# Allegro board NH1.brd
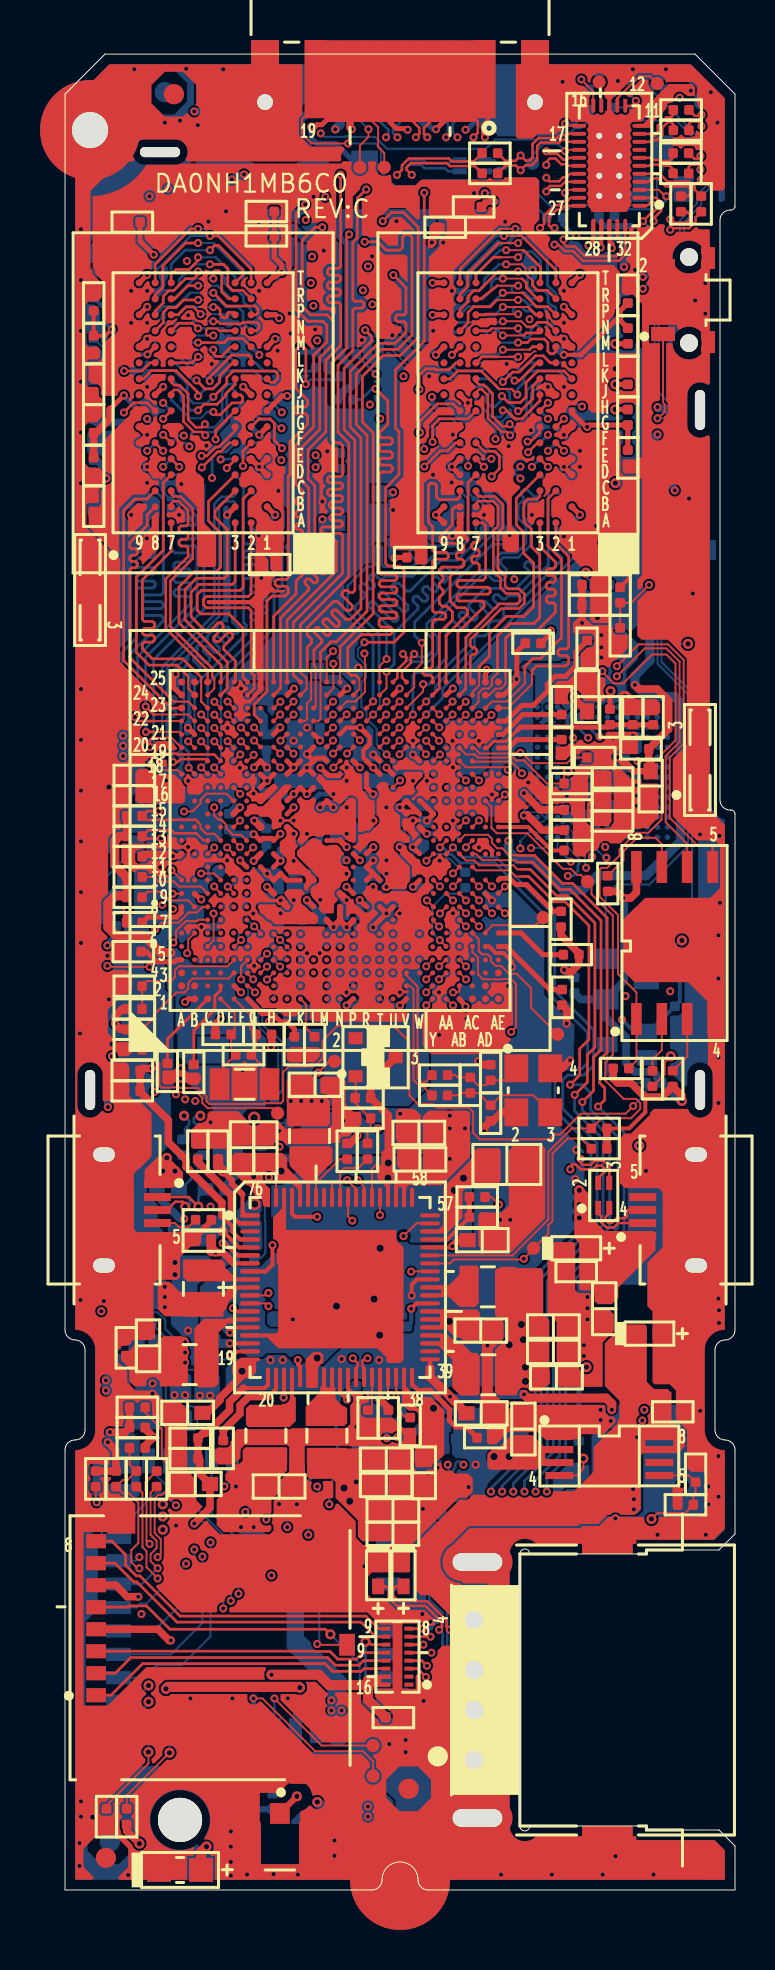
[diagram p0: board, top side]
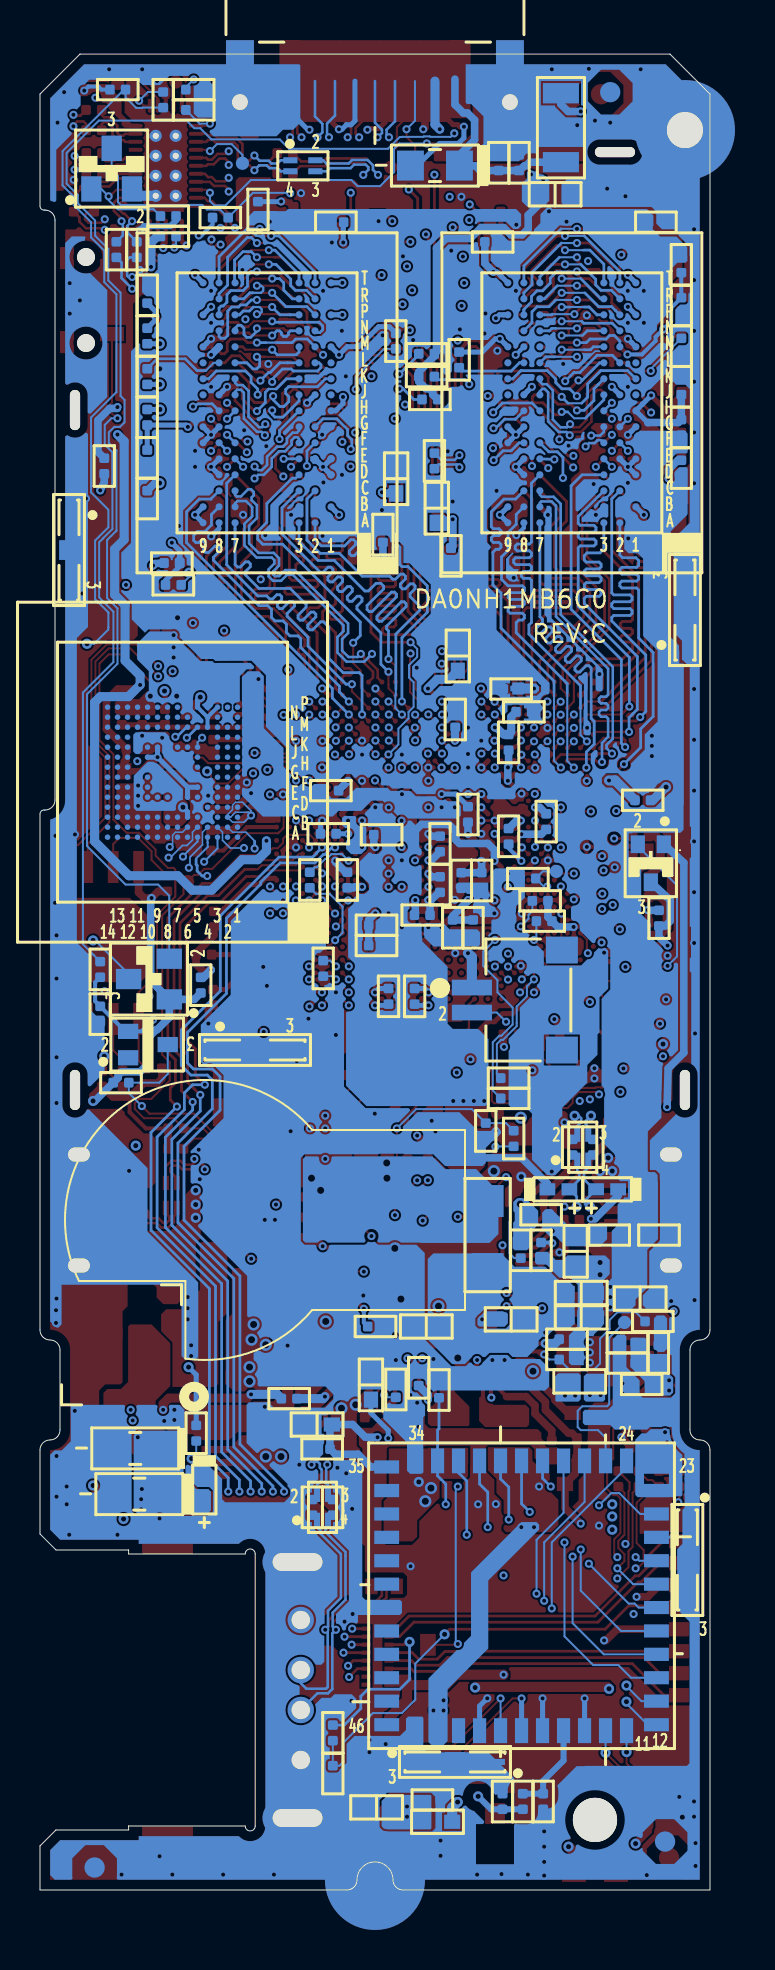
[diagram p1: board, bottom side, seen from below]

Outline 33.5 x 91.8 mm; copper layers: TOP, GND, IN1, IN2, VCC, BOTTOM. Coordinates in mm from the lower left corner of the outline.
Outline path: 0,89.8 2,91.8 31.5,91.8 33.5,89.8 33.5,84.2 arc(33.44,84.06) 33.3,84 33.25,84 arc(32.9,83.85) 32.75,83.5 32.75,54.5 arc(32.9,54.15) 33.25,54 33.3,54 arc(33.44,53.94) 33.5,53.8 33.5,28 arc(33.35,27.65) 33,27.5 arc(32.65,27.35) 32.5,27 32.5,23 arc(32.65,22.65) 33,22.5 arc(33.35,22.35) 33.5,22 33.5,17.8 32.7,17 29.07,17 29.07,16.8 23.24,16.8 arc(22.99,17.05) 22.74,16.8 22.74,3.2 arc(22.99,2.95) 23.24,3.2 29.07,3.2 29.07,3 32.7,3 33.5,2.2 33.5,0 18.15,0 arc(17.8,0.15) 17.65,0.5 arc(16.75,1.4) 15.85,0.5 arc(15.7,0.15) 15.35,0 0,0 0,22 arc(0.15,22.35) 0.5,22.5 arc(0.85,22.65) 1,23 1,27 arc(0.85,27.35) 0.5,27.5 arc(0.15,27.65) 0,28 0,89.8

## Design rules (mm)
constraint set DEFAULT: min track width 0.102
net group DFP-S4(3: nets DDI0_HDMI_SCL DDI0_HDMI_SDA
net group DFP-S4(6)W5.15(4.6)-T12B: nets M0_CLK0_DN M0_CLK0_DP M0_DQS0_DN M0_DQS0_DP M0_DQS1_DN M0_DQS1_DP M0_DQS2_DN M0_DQS2_DP M0_DQS3_DN M0_DQS3_DP M0_DQS4_DN M0_DQS4_DP M0_DQS5_DN M0_DQS5_DP M0_DQS6_DN M0_DQS6_DP M0_DQS7_DN M0_DQS7_DP PMIC_USB2_DN PMIC_USB2_DP
net group DFP-S4W5.14(4.6)-T12B: nets DDI0_HDMI_CLK_DN DDI0_HDMI_CLK_DN_ALS DDI0_HDMI_CLK_DN_CH DDI0_HDMI_CLK_DP DDI0_HDMI_CLK_DP_ALS DDI0_HDMI_CLK_DP_CH DDI0_HDMI_D0_DN DDI0_HDMI_D0_DN_ALS DDI0_HDMI_D0_DP DDI0_HDMI_D0_DP_ALS DDI0_HDMI_D1_DN DDI0_HDMI_D1_DN_ALS DDI0_HDMI_D1_DP DDI0_HDMI_D1_DP_ALS DDI0_HDMI_D2_DN DDI0_HDMI_D2_DN_ALS DDI0_HDMI_D2_DP DDI0_HDMI_D2_DP_ALS
net group DFP-S6W5.14(4.6)-T12B: nets DDI0_TX0_DN DDI0_TX0_DP DDI0_TX1_DN DDI0_TX1_DP DDI0_TX2_DN DDI0_TX2_DP DDI0_TX3_DN DDI0_TX3_DP
net group GND: nets +V1P0A +V1P0SX +V1P2SX +V1P8A +V3P3A +V_VCC +V_VNN +VDDI_EMMC +VDDQ GND
net group W5.5(4)-T12B: nets EMMC_CLK EMMC_CMD EMMC_DATA_0 EMMC_DATA_1 EMMC_DATA_2 EMMC_DATA_3 EMMC_DATA_4 EMMC_DATA_5 EMMC_DATA_6 EMMC_DATA_7 M0_BS0 M0_BS1 M0_BS2 M0_CASB M0_CKE0 M0_CS0_B M0_DATA0 M0_DATA1 M0_DATA2 M0_DATA3 M0_DATA4 M0_DATA5 M0_DATA6 M0_DATA7 M0_DATA8 M0_DATA9 M0_DATA10 M0_DATA11 M0_DATA12 M0_DATA13 M0_DATA14 M0_DATA15 M0_DATA16 M0_DATA17 M0_DATA18 M0_DATA19 M0_DATA20 M0_DATA21 M0_DATA22 M0_DATA23 M0_DATA24 M0_DATA25 M0_DATA26 M0_DATA27 M0_DATA28 M0_DATA29 M0_DATA30 M0_DATA31 M0_DATA32 M0_DATA33 M0_DATA34 M0_DATA35 M0_DATA36 M0_DATA37 M0_DATA38 M0_DATA39 M0_DATA40 M0_DATA41 M0_DATA42 M0_DATA43 M0_DATA44 M0_DATA45 M0_DATA46 M0_DATA47 M0_DATA48 M0_DATA49 M0_DATA50 M0_DATA51 M0_DATA52 M0_DATA53 M0_DATA54 M0_DATA55 M0_DATA56 M0_DATA57 M0_DATA58 M0_DATA59 M0_DATA60 M0_DATA61 M0_DATA62 M0_DATA63 M0_DM0 M0_DM1 M0_DM2 M0_DM3 M0_DM4 M0_DM5 M0_DM6 M0_DM7 M0_MA0 M0_MA1 M0_MA2 M0_MA3 M0_MA4 M0_MA5 M0_MA6 M0_MA7 M0_MA8 M0_MA9 M0_MA10 M0_MA11 M0_MA12 M0_MA13 M0_MA14 M0_ODT0 M0_RASB M0_WEB SDMMC2_CLK SDMMC2_CMD SDMMC2_D_0 SDMMC2_D_1 SDMMC2_D_2 SDMMC2_D_3 SDMMC3_CLK SDMMC3_CLK_CONN SDMMC3_CMD SDMMC3_CMD_CONN SDMMC3_D_0 SDMMC3_D_1 SDMMC3_D_2 SDMMC3_D_3 SDMMC3_DATA0_CONN SDMMC3_DATA1_CONN SDMMC3_DATA2_CONN SDMMC3_DATA3_CONN
net group W8-T12B: nets +V1P2A +V3P3A_SD +V3P3S_WIFI +V_HDMI_CONN +V_IPSOUT +V_VBUS +V_VTT +VREFCAU +VREFDQL +VRTC +VRTC_CH +VSDIO

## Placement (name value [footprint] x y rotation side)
ANT1001  h.fl-r-smt(10)  [ANTENNA-U-FL-R-SMT-1]  10.75 2.3 0 top
C1AM1  0.47u/6.3v/x5r_4  [CC0402]  18.7 83.39 180 bottom
C1AM2  0.47u/6.3v/x5r_4  [CC0402]  12.95 66.71 90 bottom
C1AM3  0.47u/6.3v/x5r_4  [CC0402]  20.43 84.16 0 top
C1AM4  0.47u/6.3v/x5r_4  [CC0402]  3.36 83.39 0 top
C1AM5  0.1u/16v/x7r_4  [CC0402]  1.43 79.23 270 bottom
C1AM6  0.1u/16v/x7r_4  [CC0402]  1.43 75.16 90 bottom
C1AM7  0.47u/6.3v/x5r_4  [CC0402]  10.07 83.93 0 top
C1AM8  0.47u/6.3v/x5r_4  [CC0402]  10.23 66.27 180 top
C1AM9  0.47u/6.3v/x5r_4  [CC0402]  10.87 82.4 0 bottom
C1AM10  0.47u/6.3v/x5r_4  [CC0402]  26.23 65.26 180 top
C1AM11  0.1u/16v/x7r_4  [CC0402]  1.43 77.32 270 top
C1AM12  0.1u/16v/x7r_4  [CC0402]  1.43 73.26 90 top
C1AM13  0.47u/6.3v/x5r_4  [CC0402]  1.43 75.29 270 top
C1AM14  0.47u/6.3v/x5r_4  [CC0402]  10.07 82.71 0 top
C1AM15  0.47u/6.3v/x5r_4  [CC0402]  19.01 83.14 180 top
C1AM16  0.47u/6.3v/x5r_4  [CC0402]  28.14 75.67 270 top
C1AM17  0.1u/16v/x7r_4  [CC0402]  28.14 77.7 270 top
C1AM18  0.1u/16v/x7r_4  [CC0402]  28.14 73.64 90 bottom
C1AM19  0.47u/6.3v/x5r_4  [CC0402]  17.49 66.63 180 top
C1AM20  0.47u/6.3v/x5r_4  [CC0402]  1.43 69.19 90 top
C1AM21  0.47u/6.3v/x5r_4  [CC0402]  26.23 64.24 180 top
C1AM22  0.47u/6.3v/x5r_4  [CC0402]  16.35 67.77 270 bottom
C1AM23  0.1u/16v/x7r_4  [CC0402]  28.14 77.7 270 bottom
C1AM24  0.1u/16v/x7r_4  [CC0402]  28.14 73.64 90 top
C1AM25  4.7u/10v/x5r_6  [CC0603]  7.74 84.79 0 bottom
C1AM33  4.7u/10v/x5r_6  [CC0603]  15.69 70.57 90 bottom
C1AM35  4.7u/10v/x5r_6  [CC0603]  13.66 69.09 90 bottom
C1AM36  4.7u/10v/x5r_6  [CC0603]  12.61 61.7 90 bottom
C1AP1  10u/10v/x5r_6  [CC0603]  14.18 28.17 180 bottom
C1AP2  22u/6.3v_6  [CC0603]  16.39 17.81 180 top
C1AP3  22u/6.3v_6  [CC0603]  16.39 18.98 180 top
C1AP4  10u/10v/x5r_6  [CC0603]  10.02 37.11 270 top
C1AP5  10u/10v/x5r_6  [CC0603]  9.94 28.53 180 bottom
C1AP6  22u/6.3v_6  [CC0603]  12.51 40.26 180 top
C1AP7  22u/6.3v_6  [CC0603]  4.15 27.21 270 top
C1AP8  10u/10v/x5r_6  [CC0603]  6.44 29.85 0 bottom
C1AP9  22u/6.3v_6  [CC0603]  3.49 29.57 0 bottom
C1AP10  22u/6.3v_6  [CC0603]  24.57 25.63 180 top
C1AP11  22u/6.3v_6  [CC0603]  24.42 26.9 180 top
C1AP12  10u/10v/x5r_6  [CC0603]  6.44 28.63 0 bottom
C1AP13  22u/6.3v_6  [CC0603]  10.7 20.17 180 top
C1AP14  10u/10v/x5r_6  [CC0603]  17.69 37.85 0 top
C1AP15  4.7u/16v_8  [CC0805]  22.09 36.28 180 top
C1AP16  4.7u/6.3v_4  [CC0402]  7.66 36.94 270 top
C1AP17  1u/6.3v_4  [CC0402]  9.94 60.05 0 bottom
C1AP18  1u/6.3v_4  [CC0402]  9.31 58.91 180 bottom
C1AP19  1u/6.3v_4  [CC0402]  12.74 58.53 90 bottom
C1AP20  4.7u/10v/x5r_6  [CC0603]  6.13 23.86 0 top
C1AP21  4.7u/6.3v_4  [CC0402]  15.15 23.6 90 top
C1AP22  4.7u/6.3v_4  [CC0402]  16.16 23.6 90 top
C1AP23  4.7u/6.3v_4  [CC0402]  17.26 23.23 90 top
C1AP24  4.7u/6.3v_4  [CC0402]  7.91 22.08 90 top
C1AP25  4.7u/6.3v_4  [CC0402]  6.26 22.59 0 top
C1AP26  4.7u/6.3v_4  [CC0402]  7.15 26.52 0 bottom
C1AP27  4.7u/6.3v_4  [CC0402]  7.15 27.54 0 bottom
C1AP28  4.7u/10v/x5r_6  [CC0603]  20.81 23.83 180 top
C1AP29  4.7u/6.3v_4  [CC0402]  6.64 36.94 270 top
C1AP31  4.7u/10v/x5r_6  [CC0603]  17.94 20.86 90 top
C1AP32  4.7u/6.3v_4  [CC0402]  3.36 39.96 0 top
C1AP33  4.7u/6.3v_4  [CC0402]  8.44 31.98 90 bottom
C1AP34  10u/10v/x5r_6  [CC0603]  17.74 36.53 0 top
C1AP35  10u/10v/x5r_6  [CC0603]  20.86 32.49 180 top
C1AP36  4.7u/6.3v_4  [CC0402]  6.92 32.44 0 top
C1AP37  4.7u/10v/x5r_6  [CC0603]  8.85 37.11 270 top
C1AP38  1u/6.3v/x5r_4  [CC0402]  20.61 33.63 180 top
C1AP40  1u/6.3v/x5r_4  [CC0402]  20.99 22.61 180 top
C1AP41  4.7u/10v/x5r_6  [CC0603]  6.72 31.93 90 bottom
C1AP42  10u/10v/x5r_6  [CC0603]  20.79 27.97 180 top
C1AP43  22u/6.3v_6  [CC0603]  16.06 21.52 180 top
C1AP44  22u/6.3v_6  [CC0603]  16.06 20.25 180 top
C1AP45  22u/6.3v_6  [CC0603]  24.42 28.17 180 top
C1AS4  1u/6.3v/x5r_4  [CC0402]  3.46 45.19 0 top
C1AS5  1u/6.3v/x5r_4  [CC0402]  3.46 42.02 0 top
C1AS63  27p/50v/npo_4  [CC0402]  21.28 40.87 270 top
C1AS64  27p/50v/npo_4  [CC0402]  21.28 38.84 90 top
C1AS65  0.1u/16v/x7r_4  [CC0402]  6.44 40.88 90 top
C1AS66  22p/50v/c0g_4  [CC0402]  7.91 42.78 0 top
C1AS67  22p/50v/c0g_4  [CC0402]  9.94 42.78 180 top
C1AS68  *1u/6.3v/x5r_4  [CC0402]  3.46 54.72 0 top
C1AS69  1u/6.3v/x5r_4  [CC0402]  11.42 50.47 270 bottom
C1AS70  1u/6.3v/x5r_4  [CC0402]  23.4 62.34 180 top
C1AS71  0.1u/16v/x7r_4  [CC0402]  28.39 58.65 90 top
C1AS72  1u/6.3v/x5r_4  [CC0402]  18.13 50.5 270 bottom
C1AS75  1u/6.3v/x5r_4  [CC0402]  3.46 55.73 0 top
C1AS76  *1u/6.3v/x5r_4  [CC0402]  3.36 54.49 0 bottom
C1AS77  1u/6.3v/x5r_4  [CC0402]  10.07 57.38 270 bottom
C1AS78  *1u/6.3v/x5r_4  [CC0402]  12.43 50.47 270 bottom
C1AS79  1u/6.3v/x5r_4  [CC0402]  16.67 48.24 180 bottom
C1AS80  *1u/6.3v/x5r_4  [CC0402]  16.42 52.76 180 bottom
C1AS81  1u/6.3v/x5r_4  [CC0402]  16.67 47.22 180 bottom
C1AS84  1u/6.3v/x5r_4  [CC0402]  22.6 84.03 270 bottom
C1AS85  *1u/6.3v/x5r_4  [CC0402]  2.7 83.39 0 bottom
C1AS86  1u/6.3v/x5r_4  [CC0402]  1.43 71.1 270 bottom
C1AS87  1u/6.3v/x5r_4  [CC0402]  28.14 69.58 270 bottom
C1AS88  *1u/6.3v/x5r_4  [CC0402]  12.86 48.11 270 bottom
C1AS89  1u/6.3v/x5r_4  [CC0402]  11.85 48.11 270 bottom
C1AS90  1u/6.3v/x5r_4  [CC0402]  8.19 53.42 270 bottom
C1AS91  1u/6.3v/x5r_4  [CC0402]  27.38 53.45 180 top
C1AS92  1u/6.3v/x5r_4  [CC0402]  27.38 54.46 180 top
C1AS93  *1u/6.3v/x5r_4  [CC0402]  3.46 51.67 0 top
C1AS94  *1u/6.3v/x5r_4  [CC0402]  13.5 50.27 90 bottom
C1AS95  1u/6.3v/x5r_4  [CC0402]  13.5 52.3 90 bottom
C1AS96  1u/6.3v/x5r_4  [CC0402]  14.39 48.75 0 bottom
C1AS97  1u/6.3v/x5r_4  [CC0402]  12.1 53.78 270 bottom
C1AS99  1u/6.3v/x5r_4  [CC0402]  10.07 52.68 270 bottom
C1AS116  1u/6.3v/x5r_4  [CC0402]  19.09 52.81 180 bottom
C1AS200  *1u/6.3v/x5r_4  [CC0402]  25.34 54.01 180 top
C1AS201  1u/6.3v/x5r_4  [CC0402]  18.96 54.97 0 bottom
C1EMMC1  0.1u/16v_4  [CC0402]  28.8 57.05 180 top
C1EMMC2  0.1u/16v_4  [CC0402]  25.34 52.99 0 top
C1EMMC3  0.1u/16v_4  [CC0402]  27.38 55.61 0 top
C1EMMC4  4.7u/10v/x5r_6  [CC0603]  29.28 55.2 270 top
C1EMMC5  4.7u/10v/x5r_6  [CC0603]  26.11 59.67 90 top
C1HDMI1  0.1u/16v_4  [CC0402]  30.81 87.99 180 top
C1HDMI2  0.1u/16v_4  [CC0402]  30.81 89.01 180 top
C1HDMI3  0.1u/16v_4  [CC0402]  30.79 85.83 180 top
C1HDMI4  0.1u/16v_4  [CC0402]  30.79 86.85 180 top
C1HDMI5  0.1u/16v_4  [CC0402]  30.79 84.31 90 top
C1HDMI6  0.1u/16v_4  [CC0402]  31.81 84.31 90 top
C1HDMI7  0.1u/16v_4  [CC0402]  28.66 82.02 90 bottom
C1HDMI8  0.1u/16v_4  [CC0402]  29.68 82.02 90 bottom
C1HDMI9  100u/6.3v_a  [CC3216]  13.75 86.23 0 bottom
C1HDMI10  1000p/50v/x7r_4  [CC0402]  10.56 86.37 90 bottom
C1HDMI11  0.1u/16v_4  [CC0402]  25.82 89.01 180 bottom
C1P1  1000p/50v/x7r_4  [CC0402]  25.56 30.92 0 top
C1P2  4.7u/10v/x5r_6  [CC0603]  26.96 29.06 90 top
C1P3  100p/50v/npo_4  [CC0402]  30.49 43.79 90 bottom
C1RTC1  1u/6.3v/x5r_4  [CC0402]  2.55 48.6 270 bottom
C1SD1  0.1u/16v_4  [CC0402]  6.26 21.57 0 top
C1SD2  10u/10v/x5r_6  [CC0603]  6.51 20.3 0 top
C1SPI1  0.1u/16v_4  [CC0402]  26.91 66.35 180 bottom
C1USB1  100u/6.3v_a  [CC3216]  28.53 19.79 0 bottom
C1USB3  100u/6.3v_a  [CC3216]  28.74 22.08 0 bottom
C1WF1  10u/10v/x5r_6  [CC0603]  16.67 4.13 0 bottom
C1WF2  0.1u/16v_4  [CC0402]  13.88 4.5 180 bottom
C1WF7  *2p/50v_4  [CC0402]  10.37 4.42 90 bottom
C1WF8  *2p/50v_4  [CC0402]  8.34 4.42 270 bottom
C1WF9  10u/10v/x5r_6  [CC0603]  19.64 23.27 0 bottom
C1WF10  0.1u/16v_4  [CC0402]  19.39 22.05 0 bottom
C1WF11  0.1u/16v_4  [CC0402]  3.41 25.28 0 bottom
C1WF12  0.1u/16v_4  [CC0402]  4.13 27.36 0 bottom
C1WF13  1u/6.3v/x5r_4  [CC0402]  4.13 26.34 0 bottom
C1WF21  *5.6p/50v_4  [CC0402]  13.55 25 90 bottom
C73  lxes15aaa1-117  [CC0603]  16.95 25.25 270 bottom
C88  0.1u/16v_4  [CC0402]  16.42 8.62 0 top
C414  0.1u/16v/x7r_4  [CC0402]  31.53 20.78 90 top
C415  4.7u/10v_6  [CC0603]  22.92 23.04 90 top
C417  0.1u/16v/x7r_4  [CC0402]  30.39 23.91 0 top
C418  *0.1u/16v_4  [CC0402]  18.86 5.82 270 bottom
CN15  50281-0020l  [88266-020L-2P-R-SMT]  7.85 44.5 90 bottom
CR1AP1  bav99  [D-SOT23_213-2_3-1_9]  15.53 41.64 180 top
CR1P1  pesd5v0u1bb  [D-SOD523-1_2X0_8-0_65H]  25.56 32.09 0 top
CR1P2  *bat54aw  [UMT_213-3-1_3]  28.1 42.27 0 bottom
CR1P3  17-21/t1d-dp2r1ty/3t  [LED17-21-T1D-DP2R1TY-3T]  5.75 1 0 top
CR1RTC1  bat54c  [SOT323_123-2_1-1_3]  2.96 51.34 90 bottom
CR1USB1  az5125-01h  [D-SOD523-1_2X0_8-0_65H]  15.66 15.73 270 top
CR1USB2  az5125-01h  [D-SOD523-1_2X0_8-0_65H]  16.93 15.73 270 top
CR1USB3  az5125-01h  [D-SOD523-1_2X0_8-0_65H]  29.22 27.82 0 top
CR1USB4  az5125-01h  [D-SOD523-1_2X0_8-0_65H]  25.28 20.02 270 bottom
CR2USB1  *az5125-01h  [D-SOD523-1_2X0_8-0_65H]  7.58 35.03 180 bottom
CR2USB2  *az5125-01h  [D-SOD523-1_2X0_8-0_65H]  5.14 35.03 0 bottom
EU1HDMI1  ps8203  [TQFN32-3X6-4-41P-0_8H]  27.21 86.21 180 top
EU1SPI1  w25q64fwssig  [SOIC8-8-1_27]  30.48 47.35 180 top
FB1WF2  mmz1608r601at(600,0.5a)  [RC0603]  6.51 25.43 0 bottom
FB1WF3  inductor_3  [RC0402]  9.36 4.42 270 bottom
H1  *h-o20x79d20x79n  [H-O20X79D20X79N]  1.25 40 0 top
H2  *h-o20x79d20x79n  [H-O20X79D20X79N]  31.75 40 0 top
H3  *h-o20x79d20x79n  [H-O20X79D20X79N]  31.75 74 0 top
H4  *h-o20x79d20x79n  [H-O20X79D20X79N]  4.75 86.9 90 top
H5  *h-c197d71p2  [H-C197D71P2]  1.25 88 0 top
H6  *h-o20x79d20x79n  [H-C87D87N]  5.75 3.5 0 top
J1HDMI1  ?  [HDMI-2HP1506-000111F-19P]  16.75 89.4 180 top
J1P1  2ub1000-000201f  [USB-2UB1000-000201F-5P-L-SMT]  31.55 34 90 top
J1SD1  158-1000902600  [SDCARD-158-1000902600-9P]  2.8 12.11 270 top
J1USB2  *2ub1000-000201f  [USB-2UB1000-000201F-5P-L-SMT]  1.95 34 270 top
J1USB3  c10784-104a3-l  [USB-020173MR004S592ZL-4P-R-V]  20.67 10 90 top
L1AP1  1uh/3a  [L2_5X2-1_2]  13.09 22.71 90 top
L1AP2  1uh/3a  [L2_5X2-1_2]  12.23 37.7 270 top
L1AP3  1uh/3a  [L2_5X2-1_2]  6.23 26.27 0 top
L1AP4  1uh/3a  [L2_5X2-1_2]  6.92 30.05 90 top
L1AP5  1uh/3a  [L2_5X2-1_2]  21.17 25.76 0 top
L1AP6  1uh/3a  [L2_5X2-1_2]  21.14 30.15 0 top
L1AP7  1uh/3a  [L2_5X2-1_2]  10.04 22.71 270 top
L1HDMI1  *exc24cg900u_nc  [CHOKE-DLP11SN900HL2L-4P-1]  20.36 86.21 180 bottom
L1USB1  exc24cg900u_nc  [CHOKE-DLP11SN900HL2L-4P-1]  19.38 19.13 90 bottom
L1USB2  *exc24cg900u_nc  [CHOKE-DLP11SN900HL2L-4P-1]  6.36 37.14 90 bottom
L1USB3  exc24cg900u_nc  [CHOKE-DLP11SN900HL2L-4P-1]  26.93 34.73 90 top
NOREF  -  [unnamed]  5.45 89.79 0 top
NOREF#2  -  [unnamed]  17.18 5.06 0 top
NOREF#3  -  [#2]  0.06 -35.81 0 top
NOREF#4  -  [unnamed]  2.04 1.61 0 top
NOREF#5  -  [#2]  159.78 -20.34 0 top
NOREF#6  -  [unnamed]  4.99 89.9 180 bottom
NOREF#7  -  [unnamed]  2.25 2.42 180 bottom
NOREF#8  -  [unnamed]  30.77 1.12 180 bottom
NOREF#9  -  [#2]  29.42 27.26 180 bottom
PAD3  *pad  [SPAD-C197]  16.75 0.5 0 top
PAD4  *pad  [SPAD-C197]  16.75 0.5 180 bottom
Q1HDMI2  2n7002k  [SOT23_123-3_3-2]  29.92 86.07 270 bottom
Q1HDMI3  2n7002k  [SOT23_123-3_3-2]  28.05 45.55 180 bottom
R1AM1  240_4  [RC0402]  1.43 77.2 90 bottom
R1AM2  240_4  [RC0402]  12.54 76.51 270 bottom
R1AM3  240_4  [RC0402]  15.71 77.45 270 bottom
R1AM4  240_4  [RC0402]  28.14 75.67 90 bottom
R1AM5  4.7k/f_4  [RC0402]  1.43 81.26 270 bottom
R1AM6  4.7k/f_4  [RC0402]  1.43 79.35 90 top
R1AM7  4.7k/f_4  [RC0402]  1.43 73.13 90 bottom
R1AM8  4.7k/f_4  [RC0402]  1.43 71.23 270 top
R1AM9  4.7k/f_4  [RC0402]  28.14 79.74 270 bottom
R1AM10  4.7k/f_4  [RC0402]  28.14 79.74 90 top
R1AM11  4.7k/f_4  [RC0402]  28.14 71.61 90 bottom
R1AM12  4.7k/f_4  [RC0402]  28.14 71.61 270 top
R1AM13  301_4  [RC0402]  14.17 75.67 0 bottom
R1AM20  301_4  [RC0402]  14.17 76.82 180 bottom
R1AM21  301_4  [RC0402]  14.01 74.53 180 bottom
R1AP1  0r/f_4  [RC0402]  14.11 36.94 270 top
R1AP2  10k/f_4  [RC0402]  15.71 25.02 90 bottom
R1AP3  10k/f_4  [RC0402]  9.46 31.98 270 bottom
R1AP4  0r/f_4  [RC0402]  20.61 34.65 180 top
R1AP5  0/f_4  [RC0402]  15.12 36.94 270 top
R1AP6  0.002/f_1206  [RC1206]  11.12 32.75 270 bottom
R1AP7  *470/f_4  [RC0402]  14.89 39.6 180 top
R1AP8  *10m/f_4  [RC0402]  14.89 38.59 180 top
R1AP9  *0r/f_4  [RC0402]  8.44 33.76 180 bottom
R1AP10  0r/f_4  [RC0402]  5.04 32.75 0 bottom
R1AP11  0r/f_4  [RC0402]  21.04 24.57 180 bottom
R1AP12  0r/f_4  [RC0402]  2.86 28.43 180 bottom
R1AS1  1k/f_4  [RC0402]  3.46 49.64 180 top
R1AS2  1k/f_4  [RC0402]  3.46 50.65 180 top
R1AS4  10k/f_4  [RC0402]  24.85 44.63 90 top
R1AS5  20k/f_4  [RC0402]  3.46 43.03 180 top
R1AS10  1.24k/f_4  [RC0402]  3.46 48.37 0 top
R1AS11  20k/f_4  [RC0402]  3.46 44.05 180 top
R1AS12  *10k/f_4  [RC0402]  26.49 56.62 0 top
R1AS13  1.24k/f_4  [RC0402]  5.12 40.93 90 top
R1AS26  402/f_4  [RC0402]  19.34 46.08 90 bottom
R1AS36  *10k/f_4  [RC0402]  25.34 55.33 0 top
R1AS41  150/f_4  [RC0402]  14.77 44.68 90 bottom
R1AS42  150/f_4  [RC0402]  12.48 42.27 270 top
R1AS43  49.9/f_4  [RC0402]  25.31 46.77 180 top
R1AS44  49.9/f_4  [RC0402]  24.8 48.54 90 top
R1AS45  49.9/f_4  [RC0402]  25.34 51.97 180 top
R1AS46  45.3/f_4  [RC0402]  11.47 42.27 270 top
R1AS49  49.9/f_4  [RC0402]  3.41 46.92 0 top
R1AS50  1m/j_4  [RC0402]  20.26 40.24 270 top
R1AS51  4.02k/j_4  [RC0402]  16.07 44.68 270 bottom
R1AS52  0r/f_4  [RC0402]  18.74 40.75 180 top
R1AS53  0r/f_4  [RC0402]  18.74 39.73 180 top
R1AS54  1m/j_4  [RC0402]  8.93 41.76 180 top
R1AS55  2k/f_4  [RC0402]  13.78 71.46 90 bottom
R1AS63  162/f_4  [RC0402]  26.11 62.08 270 top
R1AS64  23.2/f_4  [RC0402]  24.84 59.16 90 top
R1AS73  29.4/f_4  [RC0402]  24.84 57.13 270 top
R1AS76  4.7k/f_4  [RC0402]  29.41 58.65 90 top
R1AS77  4.7k/f_4  [RC0402]  27.25 58.65 270 top
R1HDMI1  0r/f_4  [RC0402]  27.34 89.51 270 bottom
R1HDMI2  5.9k_4  [RC0402]  25.82 90.02 180 bottom
R1HDMI3  10k_4  [RC0402]  24.48 83.62 180 bottom
R1HDMI4  2.2k_4  [RC0402]  3.46 52.68 0 top
R1HDMI5  2.2k_4  [RC0402]  3.46 53.7 0 top
R1HDMI6  100k_4  [RC0402]  27.09 83.7 180 bottom
R1HDMI8  2.2k_4  [RC0402]  29.61 90.02 180 bottom
R1HDMI9  0r/f_4  [RC0402]  21.24 85.83 0 top
R1HDMI10  0r/f_4  [RC0402]  21.24 86.85 0 top
R1P1  10k/f_4  [RC0402]  29.45 40.37 180 bottom
R1P2  1k/f_4  [RC0402]  30.49 46.03 90 bottom
R1P3  560/j_6  [RC0603]  13.62 3.41 180 bottom
R1SPI1  3.3k_4  [RC0402]  27.8 41.08 0 top
R1SPI2  3.3k_4  [RC0402]  30.39 40.57 90 top
R1SPI3  22_4  [RC0402]  29.37 40.57 90 top
R1SPI4  3.3k_4  [RC0402]  27.14 50.32 90 top
R1USB1  *0r/f_4  [RC0402]  19.88 19.13 90 bottom
R1USB2  *0r/f_4  [RC0402]  18.87 19.13 90 bottom
R1WF1  10k_4  [RC0402]  2.55 20.55 90 top
R1WF3  *10k_4  [RC0402]  3.62 24.14 0 top
R1WF4  10k_4  [RC0402]  3.08 3.66 90 top
R1WF5  *10k_4  [RC0402]  1.53 20.55 270 top
R1WF6  10k_4  [RC0402]  2.07 3.66 270 top
R1WF10  *0r/f_4  [RC0402]  3.57 20.55 270 top
R1WF11  0r/f_4  [RC0402]  4.58 20.55 90 top
R1WF12  *0r/f_4  [RC0402]  3.62 23.12 180 top
R1WF13  0r/f_4  [RC0402]  2.58 26.85 270 bottom
R1WF14  10k_4  [RC0402]  31.02 19.26 0 top
R2AS4  10k_4  [RC0402]  9.1 50.58 180 bottom
R2AS5  51/f_4  [RC0402]  8.29 48.44 180 bottom
R2AS6  51/f_4  [RC0402]  10.07 39.58 0 bottom
R2AS7  51/f_4  [RC0402]  10.07 40.59 0 bottom
R2AS8  51/f_4  [RC0402]  8.49 49.46 180 bottom
R2USB1  *0r/f_4  [RC0402]  6.87 37.14 90 bottom
R2USB2  *0r/f_4  [RC0402]  5.85 37.14 90 bottom
R2USB3  *0r/f_4  [RC0402]  6.92 33.51 0 top
R56  2.2k_4  [RC0402]  27.09 82.68 180 bottom
R57  2.2k_4  [RC0402]  30.29 71.2 270 bottom
R58  10k/f_4  [RC0402]  27.76 64.75 270 top
R59  *0/f_4  [RC0402]  27.76 62.72 270 top
R60  0r/f_4  [RC0402]  20.01 50.5 270 bottom
R62  0r/f_4  [RC0402]  25.69 22.84 270 bottom
R63  0r/f_4  [RC0402]  9.81 37.57 270 bottom
R64  *0r/f_4  [RC0402]  11.21 37.95 270 bottom
R65  *10k_4  [RC0402]  3.62 22.1 180 top
R66  0r/f_4  [RC0402]  18.86 7.85 90 bottom
R67  *4.7k/f_4  [RC0402]  26.83 65.26 0 bottom
R68  2.2k_4  [RC0402]  26.71 38.08 0 top
R69  2.2k_4  [RC0402]  26.71 37.06 0 top
RT1HDMI1  1.1a/6v/poly  [FSMD1206P150TS]  7.45 88.12 270 bottom
SHD1  shielding_clip  [EMIPAD39X39-59X12-3P]  1.25 64 90 bottom
SHD3  shielding_clip  [EMIPAD39X39-59X12-3P]  1.25 65 270 top
SHD4  shielding_clip  [EMIPAD39X39-59X12-3P]  31.75 56.5 90 top
SHD5  shielding_clip  [EMIPAD39X39-59X12-3P]  32.05 67 270 bottom
SHD6  shielding_clip  [EMIPAD39X39-59X12-3P]  1.13 16.5 270 bottom
SHD7  shielding_clip  [EMIPAD39X39-59X12-3P]  12.75 6.4 0 bottom
SHD8  shielding_clip  [EMIPAD39X39-59X12-3P]  22.75 42 180 bottom
SW1P1  mta2-wnc-q-t/r  [SW-MTA2-WNC-Q-TR-2P]  31.2 79.5 90 top
TP12  *pad  [TP2675]  15.96 86.14 0 top
TP13  *pad  [TP2675]  14.74 86.14 0 top
TP14  *pad  [TP2675]  26.71 90.4 0 top
TP16  *pad  [TP2675]  29.61 90.33 0 top
TP17  *pad  [TP2675]  23.38 86.34 180 bottom
TP18  *pad  [TP2675]  15.4 7.22 0 top
TP19  *pad  [TP2675]  15.4 5.69 0 top
TP20  *pad  [TP2675]  4.28 28.38 180 bottom
TP21  *pad  [TP2675]  24.63 42.79 0 top
TP22  *pad  [TP2675]  23.91 48.62 0 top
TP23  *pad  [TP2675]  26.12 50.42 0 top
TP24  *pad  [TP2675]  23.43 32.09 0 top
TP25  *pad  [TP2675]  13.47 41.43 0 top
TP26  *pad  [TP2675]  7.68 50.93 180 bottom
TP29  *pad  [TP2675]  10.63 38.84 0 top
TVS1  az6112-01f  [RC0402]  16.72 28.17 180 bottom
TVS2  az6112-01f  [RC0402]  14.56 25.61 90 bottom
TVS3  az6112-01f  [RC0402]  3.06 27.11 90 top
TVS4  az6112-01f  [RC0402]  3.36 40.98 180 top
TVS5  az6225-01f  [RC0402]  25.46 45.24 90 bottom
TVS6  az6225-01f  [RC0402]  2.55 32.75 180 bottom
TVS7  az6225-01f  [RC0402]  9.55 86.37 90 bottom
U1  soc_vlv2_cr_bga  [BGA592-INTEL-BAY-TRAIL-T-TEST]  13.75 52.48 0 top
U1AM1  ic ddr3 x16 fbga-96  [BGA96-HYNIX-H5TC4G63AFR]  6.91 74.36 180 top
U1AM2  ic ddr3 x16 fbga-96  [BGA96-HYNIX-H5TC4G63AFR]  6.91 74.36 0 bottom
U1AM3  ic ddr3 x16 fbga-96  [BGA96-HYNIX-H5TC4G63AFR]  22.15 74.36 180 top
U1AM4  ic ddr3 x16 fbga-96  [BGA96-HYNIX-H5TC4G63AFR]  22.15 74.36 0 bottom
U1AP1  axp288  [QFN76-9X9-4-77P-AXP288]  13.75 30.13 270 top
U1EMMC1  kingston_ke4cn3k6a_v4.5_f/w:0x03  [BGA153-SANDISK-SDIN7DP4-16G]  26.87 55.89 0 bottom
U1WF1  aw-nb168sm_v02  [MODULE-AW-NB168SM-46P]  9.42 14.71 180 bottom
U15  emif06msd2n16  [QFN16-3_5X1_2-4-17P]  16.62 11.66 90 top
U28  g547g1p81u  [MSOP8-4_9-65-G547]  27.21 21.7 270 top
Y1  cc5v-t1a 32.768khz 9.0pf +/-20ppm  [XTL-3_2X1_5-2_5-SMT]  8.98 40.29 180 top
Y2  e3fb25.0000f10e33  [XTL-3_2X2_5-2_2X1_7]  23.41 39.99 270 top

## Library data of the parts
ANT1001 = ANTENNA-U-FL-R-SMT-1
C1AM1-C1AM24 C1AP16-C1AP19 C1AP21-C1AP27 C1AP29 C1AP32 C1AP33 C1AP36 C1AP38 C1AP40 C1AS4 C1AS5 C1AS63-C1AS72 C1AS75-C1AS81 C1AS84-C1AS97 C1AS99 C1AS116 C1AS200 C1AS201 C1EMMC1-C1EMMC3 C1HDMI1-C1HDMI8 C1HDMI10 C1HDMI11 C1P1 C1P3 C1RTC1 C1SD1 C1SPI1 C1WF2 C1WF7 C1WF8 C1WF10-C1WF13 C1WF21 C88 C414 C417 C418 = CC0402
C1AM25 C1AM33 C1AM35 C1AM36 C1AP1-C1AP14 C1AP20 C1AP28 C1AP31 C1AP34 C1AP35 C1AP37 C1AP41-C1AP45 C1EMMC4 C1EMMC5 C1P2 C1SD2 C1WF1 C1WF9 C73 C415 = CC0603
C1AP15 = CC0805
C1HDMI9 C1USB1 C1USB3 = CC3216
CN15 = 88266-020L-2P-R-SMT
CR1AP1 = D-SOT23_213-2_3-1_9
CR1P1 CR1USB1-CR1USB4 CR2USB1 CR2USB2 = D-SOD523-1_2X0_8-0_65H
CR1P2 = UMT_213-3-1_3
CR1P3 = LED17-21-T1D-DP2R1TY-3T
CR1RTC1 = SOT323_123-2_1-1_3
EU1HDMI1 = TQFN32-3X6-4-41P-0_8H
EU1SPI1 = SOIC8-8-1_27
FB1WF2 R1P3 = RC0603
FB1WF3 R1AM1-R1AM13 R1AM20 R1AM21 R1AP1-R1AP5 R1AP7-R1AP12 R1AS1 R1AS2 R1AS4 R1AS5 R1AS10-R1AS13 R1AS26 R1AS36 R1AS41-R1AS46 R1AS49-R1AS55 R1AS63 R1AS64 R1AS73 R1AS76 R1AS77 R1HDMI1-R1HDMI6 R1HDMI8-R1HDMI10 R1P1 R1P2 R1SPI1-R1SPI4 R1USB1 R1USB2 R1WF1 R1WF3-R1WF6 R1WF10-R1WF14 R2AS4-R2AS8 R2USB1-R2USB3 R56-R60 R62-R69 TVS1-TVS7 = RC0402
H1-H4 = H-O20X79D20X79N
H5 = H-C197D71P2
H6 = H-C87D87N
J1HDMI1 = HDMI-2HP1506-000111F-19P
J1P1 J1USB2 = USB-2UB1000-000201F-5P-L-SMT
J1SD1 = SDCARD-158-1000902600-9P
J1USB3 = USB-020173MR004S592ZL-4P-R-V
L1AP1-L1AP7 = L2_5X2-1_2
L1HDMI1 L1USB1-L1USB3 = CHOKE-DLP11SN900HL2L-4P-1
PAD3 PAD4 = SPAD-C197
Q1HDMI2 Q1HDMI3 = SOT23_123-3_3-2
R1AP6 = RC1206
RT1HDMI1 = FSMD1206P150TS
SHD1 SHD3-SHD8 = EMIPAD39X39-59X12-3P
SW1P1 = SW-MTA2-WNC-Q-TR-2P
TP12-TP14 TP16-TP26 TP29 = TP2675
U1 = BGA592-INTEL-BAY-TRAIL-T-TEST
U1AM1-U1AM4 = BGA96-HYNIX-H5TC4G63AFR
U1AP1 = QFN76-9X9-4-77P-AXP288
U1EMMC1 = BGA153-SANDISK-SDIN7DP4-16G
U1WF1 = MODULE-AW-NB168SM-46P
U15 = QFN16-3_5X1_2-4-17P
U28 = MSOP8-4_9-65-G547
Y1 = XTL-3_2X1_5-2_5-SMT
Y2 = XTL-3_2X2_5-2_2X1_7

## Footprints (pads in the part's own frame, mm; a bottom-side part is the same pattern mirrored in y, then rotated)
88266-020L-2P-R-SMT
  rect 0.787x2.007 smd: 1(0.625,4.05) 2(-0.625,4.05)
  rect 1.346x1.6 smd: 3(2.5,-0.45) 4(-2.5,-0.45)
ANTENNA-U-FL-R-SMT-1
  rect 0.991x1.041 smd: 1(0,1.525)
  rect 1.041x2.21 smd: 2(-1.475,0) 3(1.475,0)
BGA96-HYNIX-H5TC4G63AFR
  round 0.356 smd: A1(-3.2,6) A2(-2.4,6) A3(-1.6,6) A7(1.6,6) A8(2.4,6) A9(3.2,6) B1(-3.2,5.2) B2(-2.4,5.2) B3(-1.6,5.2) B7(1.6,5.2) B8(2.4,5.2) B9(3.2,5.2) C1(-3.2,4.4) C2(-2.4,4.4) C3(-1.6,4.4) C7(1.6,4.4) C8(2.4,4.4) C9(3.2,4.4) D1(-3.2,3.6) D2(-2.4,3.6) D3(-1.6,3.6) D7(1.6,3.6) D8(2.4,3.6) D9(3.2,3.6) E1(-3.2,2.8) E2(-2.4,2.8) E3(-1.6,2.8) E7(1.6,2.8) E8(2.4,2.8) E9(3.2,2.8) F1(-3.2,2) F2(-2.4,2) F3(-1.6,2) F7(1.6,2) F8(2.4,2) F9(3.2,2) G1(-3.2,1.2) G2(-2.4,1.2) G3(-1.6,1.2) G7(1.6,1.2) G8(2.4,1.2) G9(3.2,1.2) H1(-3.2,0.4) H2(-2.4,0.4) H3(-1.6,0.4) H7(1.6,0.4) H8(2.4,0.4) H9(3.2,0.4) J1(-3.2,-0.4) J2(-2.4,-0.4) J3(-1.6,-0.4) J7(1.6,-0.4) J8(2.4,-0.4) J9(3.2,-0.4) K1(-3.2,-1.2) K2(-2.4,-1.2) K3(-1.6,-1.2) K7(1.6,-1.2) K8(2.4,-1.2) K9(3.2,-1.2) L1(-3.2,-2) L2(-2.4,-2) L3(-1.6,-2) L7(1.6,-2) L8(2.4,-2) L9(3.2,-2) M1(-3.2,-2.8) M2(-2.4,-2.8) M3(-1.6,-2.8) M7(1.6,-2.8) M8(2.4,-2.8) M9(3.2,-2.8) N1(-3.2,-3.6) N2(-2.4,-3.6) N3(-1.6,-3.6) N7(1.6,-3.6) N8(2.4,-3.6) N9(3.2,-3.6) P1(-3.2,-4.4) P2(-2.4,-4.4) P3(-1.6,-4.4) P7(1.6,-4.4) P8(2.4,-4.4) P9(3.2,-4.4) R1(-3.2,-5.2) R2(-2.4,-5.2) R3(-1.6,-5.2) R7(1.6,-5.2) R8(2.4,-5.2) R9(3.2,-5.2) T1(-3.2,-6) T2(-2.4,-6) T3(-1.6,-6) T7(1.6,-6) T8(2.4,-6) T9(3.2,-6)
BGA153-SANDISK-SDIN7DP4-16G
  round 0.279 smd: A1(-3.25,3.25) A2(-2.75,3.25) A3(-2.25,3.25) A4(-1.75,3.25) A5(-1.25,3.25) A6(-0.75,3.25) A7(-0.25,3.25) A8(0.25,3.25) A9(0.75,3.25) A10(1.25,3.25) A11(1.75,3.25) A12(2.25,3.25) A13(2.75,3.25) A14(3.25,3.25) B1(-3.25,2.75) B2(-2.75,2.75) B3(-2.25,2.75) B4(-1.75,2.75) B5(-1.25,2.75) B6(-0.75,2.75) B7(-0.25,2.75) B8(0.25,2.75) B9(0.75,2.75) B10(1.25,2.75) B11(1.75,2.75) B12(2.25,2.75) B13(2.75,2.75) B14(3.25,2.75) C1(-3.25,2.25) C2(-2.75,2.25) C3(-2.25,2.25) C4(-1.75,2.25) C5(-1.25,2.25) C6(-0.75,2.25) C7(-0.25,2.25) C8(0.25,2.25) C9(0.75,2.25) C10(1.25,2.25) C11(1.75,2.25) C12(2.25,2.25) C13(2.75,2.25) C14(3.25,2.25) D1(-3.25,1.75) D2(-2.75,1.75) D3(-2.25,1.75) D4(-1.75,1.75) D12(2.25,1.75) D13(2.75,1.75) D14(3.25,1.75) E1(-3.25,1.25) E2(-2.75,1.25) E3(-2.25,1.25) E5(-1.25,1.25) E6(-0.75,1.25) E7(-0.25,1.25) E8(0.25,1.25) E9(0.75,1.25) E10(1.25,1.25) E12(2.25,1.25) E13(2.75,1.25) E14(3.25,1.25) F1(-3.25,0.75) F2(-2.75,0.75) F3(-2.25,0.75) F5(-1.25,0.75) F10(1.25,0.75) F12(2.25,0.75) F13(2.75,0.75) F14(3.25,0.75) G1(-3.25,0.25) G2(-2.75,0.25) G3(-2.25,0.25) G5(-1.25,0.25) G10(1.25,0.25) G12(2.25,0.25) G13(2.75,0.25) G14(3.25,0.25) H1(-3.25,-0.25) H2(-2.75,-0.25) H3(-2.25,-0.25) H5(-1.25,-0.25) H10(1.25,-0.25) H12(2.25,-0.25) H13(2.75,-0.25) H14(3.25,-0.25) J1(-3.25,-0.75) J2(-2.75,-0.75) J3(-2.25,-0.75) J5(-1.25,-0.75) J10(1.25,-0.75) J12(2.25,-0.75) J13(2.75,-0.75) J14(3.25,-0.75) K1(-3.25,-1.25) K2(-2.75,-1.25) K3(-2.25,-1.25) K5(-1.25,-1.25) K6(-0.75,-1.25) K7(-0.25,-1.25) K8(0.25,-1.25) K9(0.75,-1.25) K10(1.25,-1.25) K12(2.25,-1.25) K13(2.75,-1.25) K14(3.25,-1.25) L1(-3.25,-1.75) L2(-2.75,-1.75) L3(-2.25,-1.75) L12(2.25,-1.75) L13(2.75,-1.75) L14(3.25,-1.75) M1(-3.25,-2.25) M2(-2.75,-2.25) M3(-2.25,-2.25) M4(-1.75,-2.25) M5(-1.25,-2.25) M6(-0.75,-2.25) M7(-0.25,-2.25) M8(0.25,-2.25) M9(0.75,-2.25) M10(1.25,-2.25) M11(1.75,-2.25) M12(2.25,-2.25) M13(2.75,-2.25) M14(3.25,-2.25) N1(-3.25,-2.75) N2(-2.75,-2.75) N3(-2.25,-2.75) N4(-1.75,-2.75) N5(-1.25,-2.75) N6(-0.75,-2.75) N7(-0.25,-2.75) N8(0.25,-2.75) N9(0.75,-2.75) N10(1.25,-2.75) N11(1.75,-2.75) N12(2.25,-2.75) N13(2.75,-2.75) N14(3.25,-2.75) P1(-3.25,-3.25) P2(-2.75,-3.25) P3(-2.25,-3.25) P4(-1.75,-3.25) P5(-1.25,-3.25) P6(-0.75,-3.25) P7(-0.25,-3.25) P8(0.25,-3.25) P9(0.75,-3.25) P10(1.25,-3.25) P11(1.75,-3.25) P12(2.25,-3.25) P13(2.75,-3.25) P14(3.25,-3.25)
BGA592-INTEL-BAY-TRAIL-T-TEST
  round 0.356 smd: A2(-7.921,-7.271) A3(-7.921,-6.621) A23(-7.921,6.621) A24(-7.921,7.271) A25(-7.921,7.921) AC1(6.621,-7.921) AC25(6.621,7.921) AD1(7.271,-7.921) AD2(7.271,-7.271) AD24(7.271,7.271) AD25(7.271,7.921) AE1(7.921,-7.921) AE2(7.921,-7.271) AE3(7.921,-6.621) AE23(7.921,6.621) AE24(7.921,7.271) AE25(7.921,7.921) B1(-7.271,-7.921) B2(-7.271,-7.271) B24(-7.271,7.271) B25(-7.271,7.921) C1(-6.621,-7.921) C25(-6.621,7.921)
  round 0.254 smd: A4(-7.921,-5.97) A5(-7.921,-5.299) A6(-7.921,-4.629) A8(-7.921,-3.321) A9(-7.921,-2.65) A10(-7.921,-1.979) A12(-7.921,-0.671) A13(-7.921,0) A14(-7.921,0.671) A16(-7.921,1.979) A17(-7.921,2.65) A18(-7.921,3.321) A20(-7.921,4.629) A21(-7.921,5.299) A22(-7.921,5.97) AA1(5.299,-7.921) AA2(5.299,-7.271) AA3(5.299,-6.621) AA4(5.299,-5.97) AA5(5.299,-5.299) AA6(5.32,-4.629) AA7(5.32,-3.975) AA8(5.32,-3.321) AA9(5.32,-2.65) AA10(5.32,-1.979) AA11(5.32,-1.325) AA12(5.32,-0.671) AA13(5.32,0) AA14(5.32,0.671) AA15(5.32,1.325) AA16(5.32,1.979) AA17(5.32,2.65) AA18(5.32,3.321) AA19(5.32,3.975) AA20(5.32,4.629) AA21(5.299,5.299) AA22(5.299,5.97) AA23(5.299,6.621) AA24(5.299,7.271) AA25(5.299,7.921) AB1(5.97,-7.921) AB2(5.97,-7.271) AB3(5.97,-6.621) AB4(5.97,-5.97) AB5(5.97,-5.299) AB6(5.97,-4.629) AB7(5.97,-3.975) AB8(5.97,-3.321) AB9(5.97,-2.65) AB10(5.97,-1.979) AB11(5.97,-1.325) AB12(5.97,-0.671) AB13(5.97,0) AB14(5.97,0.671) AB15(5.97,1.325) AB16(5.97,1.979) AB17(5.97,2.65) AB18(5.97,3.321) AB19(5.97,3.975) AB20(5.97,4.629) AB21(5.97,5.299) AB22(5.97,5.97) AB23(5.97,6.621) AB24(5.97,7.271) AB25(5.97,7.921) AC2(6.621,-7.271) AC3(6.621,-6.621) AC4(6.621,-5.97) AC5(6.621,-5.299) AC6(6.621,-4.629) AC7(6.621,-3.975) AC8(6.621,-3.321) AC9(6.621,-2.65) AC10(6.621,-1.979) AC11(6.621,-1.325) AC12(6.621,-0.671) AC13(6.621,0) AC14(6.621,0.671) AC15(6.621,1.325) AC16(6.621,1.979) AC17(6.621,2.65) AC18(6.621,3.321) AC19(6.621,3.975) AC20(6.621,4.629) AC21(6.621,5.299) AC22(6.621,5.97) AC23(6.621,6.621) AC24(6.621,7.271) AD3(7.271,-6.621) AD4(7.271,-5.97) AD5(7.271,-5.299) AD6(7.271,-4.629) AD8(7.271,-3.321) AD9(7.271,-2.65) AD10(7.271,-1.979) AD12(7.271,-0.671) AD13(7.271,0) AD14(7.271,0.671) AD16(7.271,1.979) AD17(7.271,2.65) AD18(7.271,3.321) AD20(7.271,4.629) AD21(7.271,5.299) AD22(7.271,5.97) AD23(7.271,6.621) AE4(7.921,-5.97) AE5(7.921,-5.299) AE6(7.921,-4.629) AE8(7.921,-3.321) AE9(7.921,-2.65) AE10(7.921,-1.979) AE12(7.921,-0.671) AE13(7.921,0) AE14(7.921,0.671) AE16(7.921,1.979) AE17(7.921,2.65) AE18(7.921,3.321) AE20(7.921,4.629) AE21(7.921,5.299) AE22(7.921,5.97) B3(-7.271,-6.621) B4(-7.271,-5.97) B5(-7.271,-5.299) B6(-7.271,-4.629) B8(-7.271,-3.321) B9(-7.271,-2.65) B10(-7.271,-1.979) B12(-7.271,-0.671) B13(-7.271,0) B14(-7.271,0.671) B16(-7.271,1.979) B17(-7.271,2.65) B18(-7.271,3.321) B20(-7.271,4.629) B21(-7.271,5.299) B22(-7.271,5.97) B23(-7.271,6.621) C2(-6.621,-7.271) C3(-6.621,-6.621) C4(-6.621,-5.97) C5(-6.621,-5.299) C6(-6.621,-4.629) C7(-6.621,-3.975) C8(-6.621,-3.321) C9(-6.621,-2.65) C10(-6.621,-1.979) C11(-6.621,-1.325) C12(-6.621,-0.671) C13(-6.621,0) C14(-6.621,0.671) C15(-6.621,1.325) C16(-6.621,1.979) C17(-6.621,2.65) C18(-6.621,3.321) C19(-6.621,3.975) C20(-6.621,4.629) C21(-6.621,5.299) C22(-6.621,5.97) C23(-6.621,6.621) C24(-6.621,7.271) D1(-5.97,-7.921) D2(-5.97,-7.271) D3(-5.97,-6.621) D4(-5.97,-5.97) D5(-5.97,-5.299) D6(-5.97,-4.629) D7(-5.97,-3.975) D8(-5.97,-3.321) D9(-5.97,-2.65) D10(-5.97,-1.979) D11(-5.97,-1.325) D12(-5.97,-0.671) D13(-5.97,0) D14(-5.97,0.671) D15(-5.97,1.325) D16(-5.97,1.979) D17(-5.97,2.65) D18(-5.97,3.321) D19(-5.97,3.975) D20(-5.97,4.629) D21(-5.97,5.299) D22(-5.97,5.97) D23(-5.97,6.621) D24(-5.97,7.271) D25(-5.97,7.921) E1(-5.299,-7.921) E2(-5.299,-7.271) E3(-5.299,-6.621) E4(-5.299,-5.97) E5(-5.299,-5.299) E6(-5.32,-4.629) E7(-5.32,-3.975) E8(-5.32,-3.321) E9(-5.32,-2.65) E10(-5.32,-1.979) E11(-5.32,-1.325) E12(-5.32,-0.671) E13(-5.32,0) E14(-5.32,0.671) E15(-5.32,1.325) E16(-5.32,1.979) E17(-5.32,2.65) E18(-5.32,3.321) E19(-5.32,3.975) E20(-5.32,4.629) E21(-5.299,5.299) E22(-5.299,5.97) E23(-5.299,6.621) E24(-5.299,7.271) E25(-5.299,7.921) F1(-4.629,-7.921) F2(-4.629,-7.271) F3(-4.629,-6.621) F4(-4.629,-5.97) F5(-4.629,-5.32) F6(-4.629,-4.629) F7(-4.67,-3.975) F8(-4.67,-3.321) F9(-4.67,-2.65) F10(-4.67,-1.979) F11(-4.67,-1.325) F12(-4.67,-0.671) F13(-4.67,0) F14(-4.67,0.671) F15(-4.67,1.325) F16(-4.67,1.979) F17(-4.67,2.65) F18(-4.67,3.321) F19(-4.67,3.975) F20(-4.629,4.629) F21(-4.629,5.32) F22(-4.629,5.97) F23(-4.629,6.621) F24(-4.629,7.271) F25(-4.629,7.921) G3(-3.975,-6.621) G4(-3.975,-5.97) G5(-3.975,-5.32) G6(-3.975,-4.67) G7(-3.976,-3.976) G8(-3.976,-3.313) G9(-3.976,-2.651) G10(-3.976,-1.988) G11(-3.976,-1.325) G12(-3.976,-0.663) G13(-3.976,0) G14(-3.976,0.663) G15(-3.976,1.325) G16(-3.976,1.988) G17(-3.976,2.651) G18(-3.976,3.313) G19(-3.976,3.976) G20(-3.975,4.67) G21(-3.975,5.32) G22(-3.975,5.97) G23(-3.975,6.621) H1(-3.321,-7.921) H2(-3.321,-7.271) H3(-3.321,-6.621) H4(-3.321,-5.97) H5(-3.321,-5.32) H6(-3.321,-4.67) H7(-3.313,-3.976) H8(-3.313,-3.313) H9(-3.313,-2.651) H10(-3.313,-1.988) H11(-3.313,-1.325) H12(-3.313,-0.663) H13(-3.313,0) H14(-3.313,0.663) H15(-3.313,1.325) H16(-3.313,1.988) H17(-3.313,2.651) H18(-3.313,3.313) H19(-3.313,3.976) H20(-3.321,4.67) H21(-3.321,5.32) H22(-3.321,5.97) H23(-3.321,6.621) H24(-3.321,7.271) H25(-3.321,7.921) J1(-2.65,-7.921) J2(-2.65,-7.271) J3(-2.65,-6.621) J4(-2.65,-5.97) J5(-2.65,-5.32) J6(-2.65,-4.67) J7(-2.651,-3.976) J8(-2.651,-3.313) J9(-2.651,-2.651) J10(-2.651,-1.988) J11(-2.651,-1.325) J12(-2.651,-0.663) J13(-2.651,0) J14(-2.651,0.663) J15(-2.651,1.325) J16(-2.651,1.988) J17(-2.651,2.651) J18(-2.651,3.313) J19(-2.651,3.976) J20(-2.65,4.67) J21(-2.65,5.32) J22(-2.65,5.97) J23(-2.65,6.621) J24(-2.65,7.271) J25(-2.65,7.921) K1(-1.979,-7.921) K2(-1.979,-7.271) K3(-1.979,-6.621) K4(-1.979,-5.97) K5(-1.979,-5.32) K6(-1.979,-4.67) K7(-1.988,-3.976) K8(-1.988,-3.313) K9(-1.988,-2.651) K10(-1.988,-1.988) K11(-1.988,-1.325) K12(-1.988,-0.663) K13(-1.988,0) K14(-1.988,0.663) K15(-1.988,1.325) K16(-1.988,1.988) K17(-1.988,2.651) K18(-1.988,3.313) K19(-1.988,3.976) K20(-1.979,4.67) K21(-1.979,5.32) K22(-1.979,5.97) K23(-1.979,6.621) K24(-1.979,7.271) K25(-1.979,7.921) L3(-1.325,-6.621) L4(-1.325,-5.97) L5(-1.325,-5.32) L6(-1.325,-4.67) L7(-1.325,-3.976) L8(-1.325,-3.313) L9(-1.325,-2.651) L10(-1.325,-1.988) L11(-1.325,-1.325) L12(-1.325,-0.663) L13(-1.325,0) L14(-1.325,0.663) L15(-1.325,1.325) L16(-1.325,1.988) L17(-1.325,2.651) L18(-1.325,3.313) L19(-1.325,3.976) L20(-1.325,4.67) L21(-1.325,5.32) L22(-1.325,5.97) L23(-1.325,6.621) M1(-0.671,-7.921) M2(-0.671,-7.271) M3(-0.671,-6.621) M4(-0.671,-5.97) M5(-0.671,-5.32) M6(-0.671,-4.67) M7(-0.663,-3.976) M8(-0.663,-3.313) M9(-0.663,-2.651) M10(-0.663,-1.988) M11(-0.663,-1.325) M12(-0.663,-0.663) M13(-0.663,0) M14(-0.663,0.663) M15(-0.663,1.325) M16(-0.663,1.988) M17(-0.663,2.651) M18(-0.663,3.313) M19(-0.663,3.976) M20(-0.671,4.67) M21(-0.671,5.32) M22(-0.671,5.97) M23(-0.671,6.621) M24(-0.671,7.271) M25(-0.671,7.921) N1(0,-7.921) N2(0,-7.271) N3(0,-6.621) N4(0,-5.97) N5(0,-5.32) N6(0,-4.67) N7(0,-3.976) N8(0,-3.313) N9(0,-2.651) N10(0,-1.988) N11(0,-1.325) N12(0,-0.663) N13(0,0) N14(0,0.663) N15(0,1.325) N16(0,1.988) N17(0,2.651) N18(0,3.313) N19(0,3.976) N20(0,4.67) N21(0,5.32) N22(0,5.97) N23(0,6.621) N24(0,7.271) N25(0,7.921) P1(0.671,-7.921) P2(0.671,-7.271) P3(0.671,-6.621) P4(0.671,-5.97) P5(0.671,-5.32) P6(0.671,-4.67) P7(0.663,-3.976) P8(0.663,-3.313) P9(0.663,-2.651) P10(0.663,-1.988) P11(0.663,-1.325) P12(0.663,-0.663) P13(0.663,0) P14(0.663,0.663) P15(0.663,1.325) P16(0.663,1.988) P17(0.663,2.651) P18(0.663,3.313) P19(0.663,3.976) P20(0.671,4.67) P21(0.671,5.32) P22(0.671,5.97) P23(0.671,6.621) P24(0.671,7.271) P25(0.671,7.921) R3(1.325,-6.621) R4(1.325,-5.97) R5(1.325,-5.32) R6(1.325,-4.67) R7(1.325,-3.976) R8(1.325,-3.313) R9(1.325,-2.651) R10(1.325,-1.988) R11(1.325,-1.325) R12(1.325,-0.663) R13(1.325,0) R14(1.325,0.663) R15(1.325,1.325) R16(1.325,1.988) R17(1.325,2.651) R18(1.325,3.313) R19(1.325,3.976) R20(1.325,4.67) R21(1.325,5.32) R22(1.325,5.97) R23(1.325,6.621) T1(1.979,-7.921) T2(1.979,-7.271) T3(1.979,-6.621) T4(1.979,-5.97) T5(1.979,-5.32) T6(1.979,-4.67) T7(1.988,-3.976) T8(1.988,-3.313) T9(1.988,-2.651) T10(1.988,-1.988) T11(1.988,-1.325) T12(1.988,-0.663) T13(1.988,0) T14(1.988,0.663) T15(1.988,1.325) T16(1.988,1.988) T17(1.988,2.651) T18(1.988,3.313) T19(1.988,3.976) T20(1.979,4.67) T21(1.979,5.32) T22(1.979,5.97) T23(1.979,6.621) T24(1.979,7.271) T25(1.979,7.921) U1(2.65,-7.921) U2(2.65,-7.271) U3(2.65,-6.621) U4(2.65,-5.97) U5(2.65,-5.32) U6(2.65,-4.67) U7(2.651,-3.976) U8(2.651,-3.313) U9(2.651,-2.651) U10(2.651,-1.988) U11(2.651,-1.325) U12(2.651,-0.663) U13(2.651,0) U14(2.651,0.663) U15(2.651,1.325) U16(2.651,1.988) U17(2.651,2.651) U18(2.651,3.313) U19(2.651,3.976) U20(2.65,4.67) U21(2.65,5.32) U22(2.65,5.97) U23(2.65,6.621) U24(2.65,7.271) U25(2.65,7.921) V1(3.321,-7.921) V2(3.321,-7.271) V3(3.321,-6.621) V4(3.321,-5.97) V5(3.321,-5.32) V6(3.321,-4.67) V7(3.313,-3.976) V8(3.313,-3.313) V9(3.313,-2.651) V10(3.313,-1.988) V11(3.313,-1.325) V12(3.313,-0.663) V13(3.313,0) V14(3.313,0.663) V15(3.313,1.325) V16(3.313,1.988) V17(3.313,2.651) V18(3.313,3.313) V19(3.313,3.976) V20(3.321,4.67) V21(3.321,5.32) V22(3.321,5.97) V23(3.321,6.621) V24(3.321,7.271) V25(3.321,7.921) W3(3.975,-6.621) W4(3.975,-5.97) W5(3.975,-5.32) W6(3.975,-4.67) W7(3.976,-3.976) W8(3.976,-3.313) W9(3.976,-2.651) W10(3.976,-1.988) W11(3.976,-1.325) W12(3.976,-0.663) W13(3.976,0) W14(3.976,0.663) W15(3.976,1.325) W16(3.976,1.988) W17(3.976,2.651) W18(3.976,3.313) W19(3.976,3.976) W20(3.975,4.67) W21(3.975,5.32) W22(3.975,5.97) W23(3.975,6.621) Y1(4.629,-7.921) Y2(4.629,-7.271) Y3(4.629,-6.621) Y4(4.629,-5.97) Y5(4.629,-5.32) Y6(4.629,-4.629) Y7(4.67,-3.975) Y8(4.67,-3.321) Y9(4.67,-2.65) Y10(4.67,-1.979) Y11(4.67,-1.325) Y12(4.67,-0.671) Y13(4.67,0) Y14(4.67,0.671) Y15(4.67,1.325) Y16(4.67,1.979) Y17(4.67,2.65) Y18(4.67,3.321) Y19(4.67,3.975) Y20(4.629,4.629) Y21(4.629,5.32) Y22(4.629,5.97) Y23(4.629,6.621) Y24(4.629,7.271) Y25(4.629,7.921)
CC0402
  custom 0.12x0.12 smd: 1(0.39,0) 2(-0.39,0)
CC0603
  rect 0.813x0.711 smd: 1(0.737,0) 2(-0.737,0)
CC0805
  rect 0.94x1.346 smd: 1(0.895,0) 2(-0.895,0)
CC3216
  rect 1.346x1.499 smd: 1(-1.225,0) 2(1.225,0)
CHOKE-DLP11SN900HL2L-4P-1
  rect 0.711x0.305 smd: 1(-0.625,0.275) 2(0.625,0.275) 3(0.625,-0.275) 4(-0.625,-0.275)
D-SOD523-1_2X0_8-0_65H
  rect 0.787x0.61 smd: 1(-0.55,0) 2(0.55,0)
D-SOT23_213-2_3-1_9
  rect 0.711x0.61 smd: 1(1,0.95) 2(1,-0.95) 3(-1,0)
EMIPAD39X39-59X12-3P
  rect 1.499x0.305 smd: 1(-1.75,0) 3(1.75,0)
  rect 0.991x0.991 smd: 2(0,0)
FSMD1206P150TS
  rect 1.016x1.803 smd: 1(-1.725,0) 2(1.725,0)
H-C87D87N
  round 2.21 hole 2.21 unplated: (0,0)
H-C197D71P2
  round 5.004 hole 1.803: 1(0,0)
H-O20X79D20X79N
  oval 0.508x2.007 hole 0.508x2.007 unplated: (0,0)
HDMI-2HP1506-000111F-19P
  rect 0.559x3.912 smd: 1(-4.5,-1.15) 2(-4,-1.15) 18(4,-1.15) 19(4.5,-1.15)
  rect 0.559x4.089 smd: 3(-3.5,-1.05) 4(-3,-1.05) 5(-2.5,-1.05) 6(-2,-1.05) 7(-1.5,-1.05) 8(-1,-1.05) 9(-0.5,-1.05) 10(0,-1.05) 11(0.5,-1.05) 12(1,-1.05) 13(1.5,-1.05) 14(2,-1.05) 15(2.5,-1.05) 16(3,-1.05) 17(3.5,-1.05)
  rect 1.397x4.597 hole 0.787: 20(-6.75,0) 21(6.75,0)
L2_5X2-1_2
  rect 0.787x2.007 smd: 1(-1,0) 2(1,0)
LED17-21-T1D-DP2R1TY-3T
  rect 1.194x1.194 smd: 1(-1.05,0) 2(1.05,0)
MODULE-AW-NB168SM-46P
  rect 0.66x1.245 smd: 1(-5.25,-6.745) 2(-4.2,-6.745) 3(-3.15,-6.745) 4(-2.1,-6.745) 5(-1.05,-6.745) 6(0,-6.745) 7(1.05,-6.745) 8(2.1,-6.745) 9(3.15,-6.745) 10(4.2,-6.745) 11(5.25,-6.745) 24(5.25,6.745) 25(4.2,6.745) 26(3.15,6.745) 27(2.1,6.745) 28(1.05,6.745) 29(0,6.745) 30(-1.05,6.745) 31(-2.1,6.745) 32(-3.15,6.745) 33(-4.2,6.745) 34(-5.25,6.745)
  rect 1.245x0.66 smd: 12(6.745,-6.45) 13(6.745,-5.27) 14(6.745,-4.1) 15(6.745,-2.93) 16(6.745,-1.76) 17(6.745,-0.59) 18(6.745,0.58) 19(6.745,1.75) 20(6.745,2.92) 21(6.745,4.09) 22(6.745,5.26) 23(6.745,6.44) 35(-6.745,6.44) 36(-6.745,5.26) 37(-6.745,4.09) 38(-6.745,2.92) 39(-6.745,1.75) 40(-6.745,0.58) 41(-6.745,-0.59) 42(-6.745,-1.76) 43(-6.745,-2.93) 44(-6.745,-4.1) 45(-6.745,-5.27) 46(-6.745,-6.45)
MSOP8-4_9-65-G547
  rect 0.356x1.397 smd: 1(-0.975,-2.5) 2(-0.325,-2.5) 3(0.325,-2.5) 4(0.975,-2.5) 5(0.975,2.5) 6(0.325,2.5) 7(-0.325,2.5) 8(-0.975,2.5)
QFN16-3_5X1_2-4-17P
  rect 0.203x0.457 smd: 1(-1.4,-0.575) 2(-1,-0.575) 3(-0.6,-0.575) 4(-0.2,-0.575) 5(0.2,-0.575) 6(0.6,-0.575) 7(1,-0.575) 8(1.4,-0.575) 9(1.4,0.575) 10(1,0.575) 11(0.6,0.575) 12(0.2,0.575) 13(-0.2,0.575) 14(-0.6,0.575) 15(-1,0.575) 16(-1.4,0.575)
  rect 2.311x0.305 smd: 17(0,0)
QFN76-9X9-4-77P-AXP288
  oval 0.203x0.991 smd: 1(-3.6,-4.5) 2(-3.2,-4.5) 3(-2.8,-4.5) 4(-2.4,-4.5) 5(-2,-4.5) 6(-1.6,-4.5) 7(-1.2,-4.5) 8(-0.8,-4.5) 9(-0.4,-4.5) 10(0,-4.5) 11(0.4,-4.5) 12(0.8,-4.5) 13(1.2,-4.5) 14(1.6,-4.5) 15(2,-4.5) 16(2.4,-4.5) 17(2.8,-4.5) 18(3.2,-4.5) 19(3.6,-4.5) 39(3.6,4.5) 40(3.2,4.5) 41(2.8,4.5) 42(2.4,4.5) 43(2,4.5) 44(1.6,4.5) 45(1.2,4.5) 46(0.8,4.5) 47(0.4,4.5) 48(0,4.5) 49(-0.4,4.5) 50(-0.8,4.5) 51(-1.2,4.5) 52(-1.6,4.5) 53(-2,4.5) 54(-2.4,4.5) 55(-2.8,4.5) 56(-3.2,4.5) 57(-3.6,4.5)
  oval 0.991x0.203 smd: 20(4.5,-3.6) 21(4.5,-3.2) 22(4.5,-2.8) 23(4.5,-2.4) 24(4.5,-2) 25(4.5,-1.6) 26(4.5,-1.2) 27(4.5,-0.8) 28(4.5,-0.4) 29(4.5,0) 30(4.5,0.4) 31(4.5,0.8) 32(4.5,1.2) 33(4.5,1.6) 34(4.5,2) 35(4.5,2.4) 36(4.5,2.8) 37(4.5,3.2) 38(4.5,3.6) 58(-4.5,3.6) 59(-4.5,3.2) 60(-4.5,2.8) 61(-4.5,2.4) 62(-4.5,2) 63(-4.5,1.6) 64(-4.5,1.2) 65(-4.5,0.8) 66(-4.5,0.4) 67(-4.5,0) 68(-4.5,-0.4) 69(-4.5,-0.8) 70(-4.5,-1.2) 71(-4.5,-1.6) 72(-4.5,-2) 73(-4.5,-2.4) 74(-4.5,-2.8) 75(-4.5,-3.2) 76(-4.5,-3.6)
  rect 5.512x5.512 smd: 77(0,0)
RC0402
  custom 0.12x0.12 smd: 1(0.39,0) 2(-0.39,0)
RC0603
  rect 0.813x0.711 smd: 1(0.737,0) 2(-0.737,0)
RC1206
  rect 1.6x1.6 smd: 1(1.702,0) 2(-1.702,0)
SDCARD-158-1000902600-9P
  rect 0.711x0.991 smd: 1(2.37,-1.25) 2(1.27,-1.25) 3(0.17,-1.25) 4(-0.93,-1.25) 5(-2.03,-1.25) 6(-3.13,-1.25) 7(-4.23,-1.25) 8(-5.33,-1.25)
  rect 1.092x0.787 smd: 9(-0.15,11.3)
  rect 0.838x1.753 smd: 10(6.375,-1.12)
  rect 0.711x2.794 smd: 11(6.45,9.85)
  rect 0.711x2.007 smd: 12(-6.45,10.25)
  rect 0.838x1.295 smd: 13(-6.375,0.05)
SOIC8-8-1_27
  rect 0.533x1.6 smd: 1(1.905,3.8) 2(0.635,3.8) 3(-0.635,3.8) 4(-1.905,3.8) 5(-1.905,-3.8) 6(-0.635,-3.8) 7(0.635,-3.8) 8(1.905,-3.8)
SOT23_123-3_3-2
  rect 1.27x1.016 smd: 1(1.016,-1.016) 2(1.016,1.016) 3(-1.016,0)
SOT323_123-2_1-1_3
  rect 0.889x0.711 smd: 1(0.95,-0.65) 2(0.95,0.65) 3(-0.95,0)
SPAD-C197
  round 5.004 smd: 1(0,0)
SW-MTA2-WNC-Q-TR-2P
  round 0.889 hole 0.889 unplated: (-2.15,0) (2.15,0)
  rect 0.711x1.194 smd: 1(-1.7,1.3) 2(1.7,1.3)
  rect 1.295x0.787 smd: 3(0,1.5)
  custom 0.175x0.175 smd: 4(-2.1,-0.95) 5(2.1,-0.95)
TP2675
  round 0.66 smd: 1(0,0)
TQFN32-3X6-4-41P-0_8H
  custom 0.05x0.05 smd: 1(-1.5,2) 2(-1.5,1.6) 3(-1.5,1.2) 4(-1.5,0.8) 5(-1.5,0.4) 6(-1.5,0) 7(-1.5,-0.4) 8(-1.5,-0.8) 9(-1.5,-1.2) 10(-1.5,-1.6) 11(-1.5,-2) 12(-0.8,-3) 13(-0.4,-3) 14(0,-3) 15(0.4,-3) 16(0.8,-3) 17(1.5,-2) 18(1.5,-1.6) 19(1.5,-1.2) 20(1.5,-0.8) 21(1.5,-0.4) 22(1.5,0) 23(1.5,0.4) 24(1.5,0.8) 25(1.5,1.2) 26(1.5,1.6) 27(1.5,2) 28(0.8,3) 29(0.4,3) 30(0,3) 31(-0.4,3) 32(-0.8,3)
  rect 1.803x4.597 smd: 33(0,0)
  round 0.61 hole 0.305: 34(-0.5,1.5) 35(-0.5,0.5) 36(-0.5,-0.5) 37(-0.5,-1.5) 38(0.5,-1.5) 39(0.5,-0.5) 40(0.5,0.5) 41(0.5,1.5)
UMT_213-3-1_3
  rect 1.016x0.762 smd: 1(0.991,0.66) 2(0.991,-0.66) 3(-0.991,0)
unnamed
  round 1.016 smd: 1(0,0)
USB-2UB1000-000201F-5P-L-SMT
  rect 0.406x1.346 smd: 1(-1.3,2.67) 2(-0.65,2.67) 3(0,2.67) 4(0.65,2.67) 5(1.3,2.67)
  rect 1.549x1.905 hole 0.711x1.092: 6(-2.775,0) 7(2.775,0)
  custom 0.25x0.25 smd: 8(-3.487,1.78) 9(3.487,1.78)
  rect 1.422x1.905 smd: 10(-0.962,0) 11(0.962,0)
USB-020173MR004S592ZL-4P-R-V
  round 1.321 hole 0.914: 1(-3.5,0.21) 2(-1,0.21) 3(1,0.21) 4(3.5,0.21)
  oval 1.905x3.505 hole 0.889x2.489: 5(-6.4,0.05) 6(6.4,0.05)
  rect 0.66x2.54 smd: 7(-7.133,-6.45)
  rect 1.397x2.54 smd: 8(7.5,-6.45)
XTL-3_2X1_5-2_5-SMT
  rect 0.991x1.6 smd: 1(-1.25,0) 2(1.25,0)
XTL-3_2X2_5-2_2X1_7
  rect 1.397x1.194 smd: 1(-1.1,-0.85) 2(1.1,-0.85) 3(1.1,0.85) 4(-1.1,0.85)

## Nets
+V1P0A: C1AP7.1 C1AS68.1 C1AS69.1 C1AS70.1 C1AS72.1 C1AS75.1 C1AS76.1 C1AS77.1 C1AS78.1 C1AS200.1 C1AS201.1 L1AP3.1 TVS3.2 U1.A16 U1.A17 U1.AE24 U1.G8 U1.G17 U1.G18 U1.G19 U1.H7 U1.H8 U1.H18 U1.J7 U1.J9 U1.J16 U1.K7 U1.K8 U1.K9 U1.K17 U1.L7 U1.L17 U1.M16 U1.M18 U1.N18 U1.R17 U1.R18 U1.U18 U1.W10 U1AP1.13
+V1P0A_LX: L1AP3.2 U1AP1.14
+V1P0SX: C1AP6.1 C1AS79.1 C1AS80.1 C1AS81.1 L1AP2.1 U1.H11 U1.H12 U1.R10 U1.R11 U1.T7 U1.T8 U1.T10 U1.U8 U1.V15 U1.V16 U1.W15 U1AP1.73
+V1P0SX_LX: L1AP2.2 U1AP1.71
+V1P2A: C1AP33.1 C1AS88.1 C1AS89.1 U1.M7 U1.N7 U1.N8 U1.P7 U1AP1.6
+V1P2SX: C1AP32.1 C1AS90.1 TVS4.2 U1.G13 U1.H13 U1.P9 U1.P12 U1.P19 U1AP1.4
+V1P8A: C1AP16.1 C1AS91.1 C1AS92.1 C1EMMC3.2 C1EMMC5.2 C1SPI1.2 EU1HDMI1.30 EU1SPI1.8 Q1HDMI3.1 R1AS1.1 R1AS2.1 R1HDMI3.2 R1HDMI4.2 R1HDMI5.2 R1P1.2 R1SPI1.2 R1SPI2.2 R1SPI4.2 R1WF14.2 R2AS4.2 R2AS6.2 R2AS7.2 R58.2 R68.1 R69.1 TVS5.2 U1.G11 U1.H10 U1.J10 U1.J15 U1.K10 U1.W12 U1.W13 U1.W16 U1.Y15 U1AP1.1 U1EMMC1.C6 U1EMMC1.M4 U1EMMC1.N4 U1EMMC1.P3 U1EMMC1.P5
+V3P3A: C1AP13.1 C1AS99.1 C1EMMC1.2 C1EMMC4.2 C1WF1.2 C1WF2.2 EU1HDMI1.11 FB1WF2.1 L1AP7.2 R1AP3.2 R1AP9.2 R1HDMI8.2 R1P3.2 R62.2 U1.G12 U1.H9 U1AP1.24 U1EMMC1.E6 U1EMMC1.F5 U1EMMC1.J10 U1EMMC1.K9 U1WF1.2
+V3P3A_LX: L1AP7.1 U1AP1.23
+V3P3A_SD: C1AP25.1 C1SD1.1 C1SD2.1 J1SD1.4 U1AP1.20
+V3P3S_WIFI: C1WF9.2 C1WF10.2 FB1WF2.2 R1WF12.2 R65.2 U1WF1.35
+VDDI_EMMC: C1EMMC2.2 U1EMMC1.C2
+VDDIO_WIFI: C1WF11.2 C1WF12.2 C1WF13.2 R1WF1.1 R1WF3.2 R1WF4.2 R1WF5.2 R1WF12.1 R1WF13.1 U1WF1.22 U1WF1.23
+VDDQ: C1AM1.2 C1AM2.2 C1AM3.2 C1AM4.2 C1AM7.2 C1AM8.2 C1AM9.2 C1AM10.2 C1AM13.2 C1AM14.2 C1AM15.2 C1AM16.2 C1AM19.2 C1AM20.2 C1AM21.2 C1AM22.2 C1AM33.1 C1AM35.1 C1AM36.1 C1AP9.1 C1AP17.1 C1AP18.1 C1AP19.1 C1AS84.1 C1AS85.1 C1AS86.1 C1AS87.1 L1AP4.1 R1AM5.2 R1AM7.2 R1AM9.2 R1AM11.2 R1AP10.2 R1AS77.2 TVS6.2 U1.K18 U1.L18 U1.L19 U1.L20 U1.M19 U1.T19 U1.W19 U1AM1.A1 U1AM1.A8 U1AM1.B2 U1AM1.C1 U1AM1.C9 U1AM1.D2 U1AM1.D9 U1AM1.E9 U1AM1.F1 U1AM1.G7 U1AM1.H2 U1AM1.H9 U1AM1.K2 U1AM1.K8 U1AM1.N1 U1AM1.N9 U1AM1.R1 U1AM1.R9 U1AM2.A1 U1AM2.A8 U1AM2.B2 U1AM2.C1 U1AM2.C9 U1AM2.D2 U1AM2.D9 U1AM2.E9 U1AM2.F1 U1AM2.G7 U1AM2.H2 U1AM2.H9 U1AM2.K2 U1AM2.K8 U1AM2.N1 U1AM2.N9 U1AM2.R1 U1AM2.R9 U1AM3.A1 U1AM3.A8 U1AM3.B2 U1AM3.C1 U1AM3.C9 U1AM3.D2 U1AM3.D9 U1AM3.E9 U1AM3.F1 U1AM3.G7 U1AM3.H2 U1AM3.H9 U1AM3.K2 U1AM3.K8 U1AM3.N1 U1AM3.N9 U1AM3.R1 U1AM3.R9 U1AM4.A1 U1AM4.A8 U1AM4.B2 U1AM4.C1 U1AM4.C9 U1AM4.D2 U1AM4.D9 U1AM4.E9 U1AM4.F1 U1AM4.G7 U1AM4.H2 U1AM4.H9 U1AM4.K2 U1AM4.K8 U1AM4.N1 U1AM4.N9 U1AM4.R1 U1AM4.R9 U1AP1.10
+VDDQ_LX: L1AP4.2 U1AP1.9
GND: ANT1001.2 ANT1001.3 C1AM1.1 C1AM2.1 C1AM3.1 C1AM4.1 C1AM5.1 C1AM6.1 C1AM7.1 C1AM8.1 C1AM9.1 C1AM10.1 C1AM11.1 C1AM12.1 C1AM13.1 C1AM14.1 C1AM15.1 C1AM16.1 C1AM17.1 C1AM18.1 C1AM19.1 C1AM20.1 C1AM21.1 C1AM22.1 C1AM23.1 C1AM24.1 C1AM25.2 C1AM33.2 C1AM35.2 C1AM36.2 C1AP1.2 C1AP2.2 C1AP3.2 C1AP4.2 C1AP5.2 C1AP6.2 C1AP7.2 C1AP8.2 C1AP9.2 C1AP10.2 C1AP11.2 C1AP12.2 C1AP13.2 C1AP14.2 C1AP15.2 C1AP16.2 C1AP17.2 C1AP18.2 C1AP19.2 C1AP20.2 C1AP21.2 C1AP22.2 C1AP23.2 C1AP24.2 C1AP25.2 C1AP26.2 C1AP27.2 C1AP28.2 C1AP29.2 C1AP31.2 C1AP32.2 C1AP33.2 C1AP34.2 C1AP35.2 C1AP36.2 C1AP37.2 C1AP38.2 C1AP40.2 C1AP41.2 C1AP42.2 C1AP43.2 C1AP44.2 C1AP45.2 C1AS4.2 C1AS5.2 C1AS63.2 C1AS64.2 C1AS65.2 C1AS66.2 C1AS67.2 C1AS68.2 C1AS69.2 C1AS70.2 C1AS71.1 C1AS72.2 C1AS75.2 C1AS76.2 C1AS77.2 C1AS78.2 C1AS79.2 C1AS80.2 C1AS81.2 C1AS84.2 C1AS85.2 C1AS86.2 C1AS87.2 C1AS88.2 C1AS89.2 C1AS90.2 C1AS91.2 C1AS92.2 C1AS93.2 C1AS94.2 C1AS95.2 C1AS96.2 C1AS97.2 C1AS99.2 C1AS116.2 C1AS200.2 C1AS201.2 C1EMMC1.1 C1EMMC2.1 C1EMMC3.1 C1EMMC4.1 C1EMMC5.1 C1HDMI9.2 C1HDMI10.1 C1HDMI11.1 C1P1.2 C1P2.2 C1P3.2 C1RTC1.2 C1SD1.2 C1SD2.2 C1SPI1.1 C1USB1.2 C1USB3.2 C1WF1.1 C1WF2.1 C1WF7.1 C1WF8.1 C1WF9.1 C1WF10.1 C1WF11.1 C1WF12.1 C1WF13.1 C1WF21.1 C73.2 C88.1 C414.1 C415.1 C417.1 C418.1 CN15.1 CR1P1.1 CR1P3.1 CR1USB1.1 CR1USB2.1 CR1USB3.2 CR1USB4.1 CR2USB1.1 CR2USB2.1 EU1HDMI1.14 EU1HDMI1.33 EU1HDMI1.34 EU1HDMI1.35 EU1HDMI1.36 EU1HDMI1.37 EU1HDMI1.38 EU1HDMI1.39 EU1HDMI1.40 EU1HDMI1.41 EU1SPI1.4 H5.1 J1HDMI1.2 J1HDMI1.5 J1HDMI1.8 J1HDMI1.11 J1HDMI1.17 J1HDMI1.20 J1HDMI1.21 J1P1.5 J1P1.6 J1P1.7 J1P1.8 J1P1.9 J1P1.10 J1P1.11 J1SD1.6 J1SD1.10 J1SD1.11 J1SD1.12 J1SD1.13 J1USB2.5 J1USB2.6 J1USB2.7 J1USB2.8 J1USB2.9 J1USB2.10 J1USB2.11 J1USB3.1 J1USB3.5 J1USB3.6 J1USB3.7 J1USB3.8 PAD3.1 PAD4.1 Q1HDMI2.2 R1AM1.2 R1AM2.2 R1AM3.2 R1AM4.2 R1AM6.1 R1AM8.1 R1AM10.1 R1AM12.1 R1AP2.1 R1AP8.1 R1AS4.2 R1AS10.2 R1AS12.1 R1AS13.2 R1AS36.1 R1AS41.1 R1AS42.1 R1AS43.2 R1AS44.2 R1AS45.2 R1AS46.1 R1AS49.2 R1AS51.2 R1AS63.1 R1AS64.1 R1AS73.1 R1AS76.1 R1HDMI2.1 R1HDMI6.1 R1WF6.1 R2AS5.1 R2AS8.1 R2USB3.1 R59.1 R64.1 R67.1 SHD1.1 SHD1.2 SHD1.3 SHD3.1 SHD3.2 SHD3.3 SHD4.1 SHD4.2 SHD4.3 SHD5.1 SHD5.2 SHD5.3 SHD6.1 SHD6.2 SHD6.3 SHD7.1 SHD7.2 SHD7.3 SHD8.1 SHD8.2 SHD8.3 SW1P1.2 SW1P1.3 SW1P1.4 SW1P1.5 TVS1.1 TVS2.1 TVS3.1 TVS4.1 TVS5.1 TVS6.1 TVS7.1 U1.A24 U1.AA2 U1.AA7 U1.AA11 U1.AA15 U1.AA18 U1.AA21 U1.AA24 U1.AD5 U1.AD9 U1.AD13 U1.AD17 U1.AD21 U1.AD25 U1.AE2 U1.B1 U1.B5 U1.B9 U1.B13 U1.B17 U1.B21 U1.E2 U1.E7 U1.E11 U1.E15 U1.E18 U1.E21 U1.E24 U1.G5 U1.G7 U1.G9 U1.G10 U1.G14 U1.G16 U1.H17 U1.H21 U1.J2 U1.J8 U1.J11 U1.J12 U1.J13 U1.J14 U1.J18 U1.J19 U1.J24 U1.K11 U1.K19 U1.L5 U1.L6 U1.L8 U1.L10 U1.L21 U1.M13 U1.M17 U1.N2 U1.N9 U1.N13 U1.N16 U1.N17 U1.N21 U1.N24 U1.P8 U1.P17 U1.P18 U1.R5 U1.R6 U1.R7 U1.R9 U1.R12 U1.R14 U1.R15 U1.R16 U1.R19 U1.R20 U1.R21 U1.T9 U1.T18 U1.U2 U1.U9 U1.U24 U1.V6 U1.V7 U1.V8 U1.V9 U1.V12 U1.V14 U1.V19 U1.V21 U1.W5 U1.W7 U1.W8 U1.W9 U1.W11 U1.W17 U1.Y11 U1AM1.A9 U1AM1.B1 U1AM1.B3 U1AM1.B9 U1AM1.D1 U1AM1.D8 U1AM1.E1 U1AM1.E2 U1AM1.E8 U1AM1.F9 U1AM1.G1 U1AM1.G8 U1AM1.G9 U1AM1.J2 U1AM1.J8 U1AM1.M1 U1AM1.M9 U1AM1.P1 U1AM1.P9 U1AM1.T1 U1AM1.T9 U1AM2.A9 U1AM2.B1 U1AM2.B3 U1AM2.B9 U1AM2.D1 U1AM2.D8 U1AM2.E1 U1AM2.E2 U1AM2.E8 U1AM2.F9 U1AM2.G1 U1AM2.G8 U1AM2.G9 U1AM2.J2 U1AM2.J8 U1AM2.M1 U1AM2.M9 U1AM2.P1 U1AM2.P9 U1AM2.T1 U1AM2.T9 U1AM3.A9 U1AM3.B1 U1AM3.B3 U1AM3.B9 U1AM3.D1 U1AM3.D8 U1AM3.E1 U1AM3.E2 U1AM3.E8 U1AM3.F9 U1AM3.G1 U1AM3.G8 U1AM3.G9 U1AM3.J2 U1AM3.J8 U1AM3.M1 U1AM3.M9 U1AM3.P1 U1AM3.P9 U1AM3.T1 U1AM3.T9 U1AM4.A9 U1AM4.B1 U1AM4.B3 U1AM4.B9 U1AM4.D1 U1AM4.D8 U1AM4.E1 U1AM4.E2 U1AM4.E8 U1AM4.F9 U1AM4.G1 U1AM4.G8 U1AM4.G9 U1AM4.J2 U1AM4.J8 U1AM4.M1 U1AM4.M9 U1AM4.P1 U1AM4.P9 U1AM4.T1 U1AM4.T9 U1AP1.16 U1AP1.30 U1AP1.49 U1AP1.74 U1AP1.77 U1EMMC1.C4 U1EMMC1.E7 U1EMMC1.G5 U1EMMC1.H10 U1EMMC1.K8 U1EMMC1.N2 U1EMMC1.N5 U1EMMC1.P4 U1EMMC1.P6 U1WF1.1 U1WF1.4 U1WF1.7 U1WF1.9 U1WF1.34 U1WF1.41 U15.17 U28.1 Y2.2 Y2.4
VDDQSET: R1AP4.2 U1AP1.66
+V_HDMI_CONN: C1HDMI9.1 C1HDMI10.2 J1HDMI1.18 RT1HDMI1.2 TVS7.2
